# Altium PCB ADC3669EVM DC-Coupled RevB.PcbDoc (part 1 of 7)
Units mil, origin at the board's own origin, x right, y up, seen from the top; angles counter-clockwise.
Board outline 5000 x 2716.54 mil, 12 copper layers (Top Layer, L2 GND, L3 SIG, L4 GND, L5 PWR, L6 GND, L7 GND, L8 PWR, L9 GND, L10 PWR, L11 GND, Bottom Layer), stack 61 mil thick; 546 components, 341 nets, 2088 pads, 1256 vias.
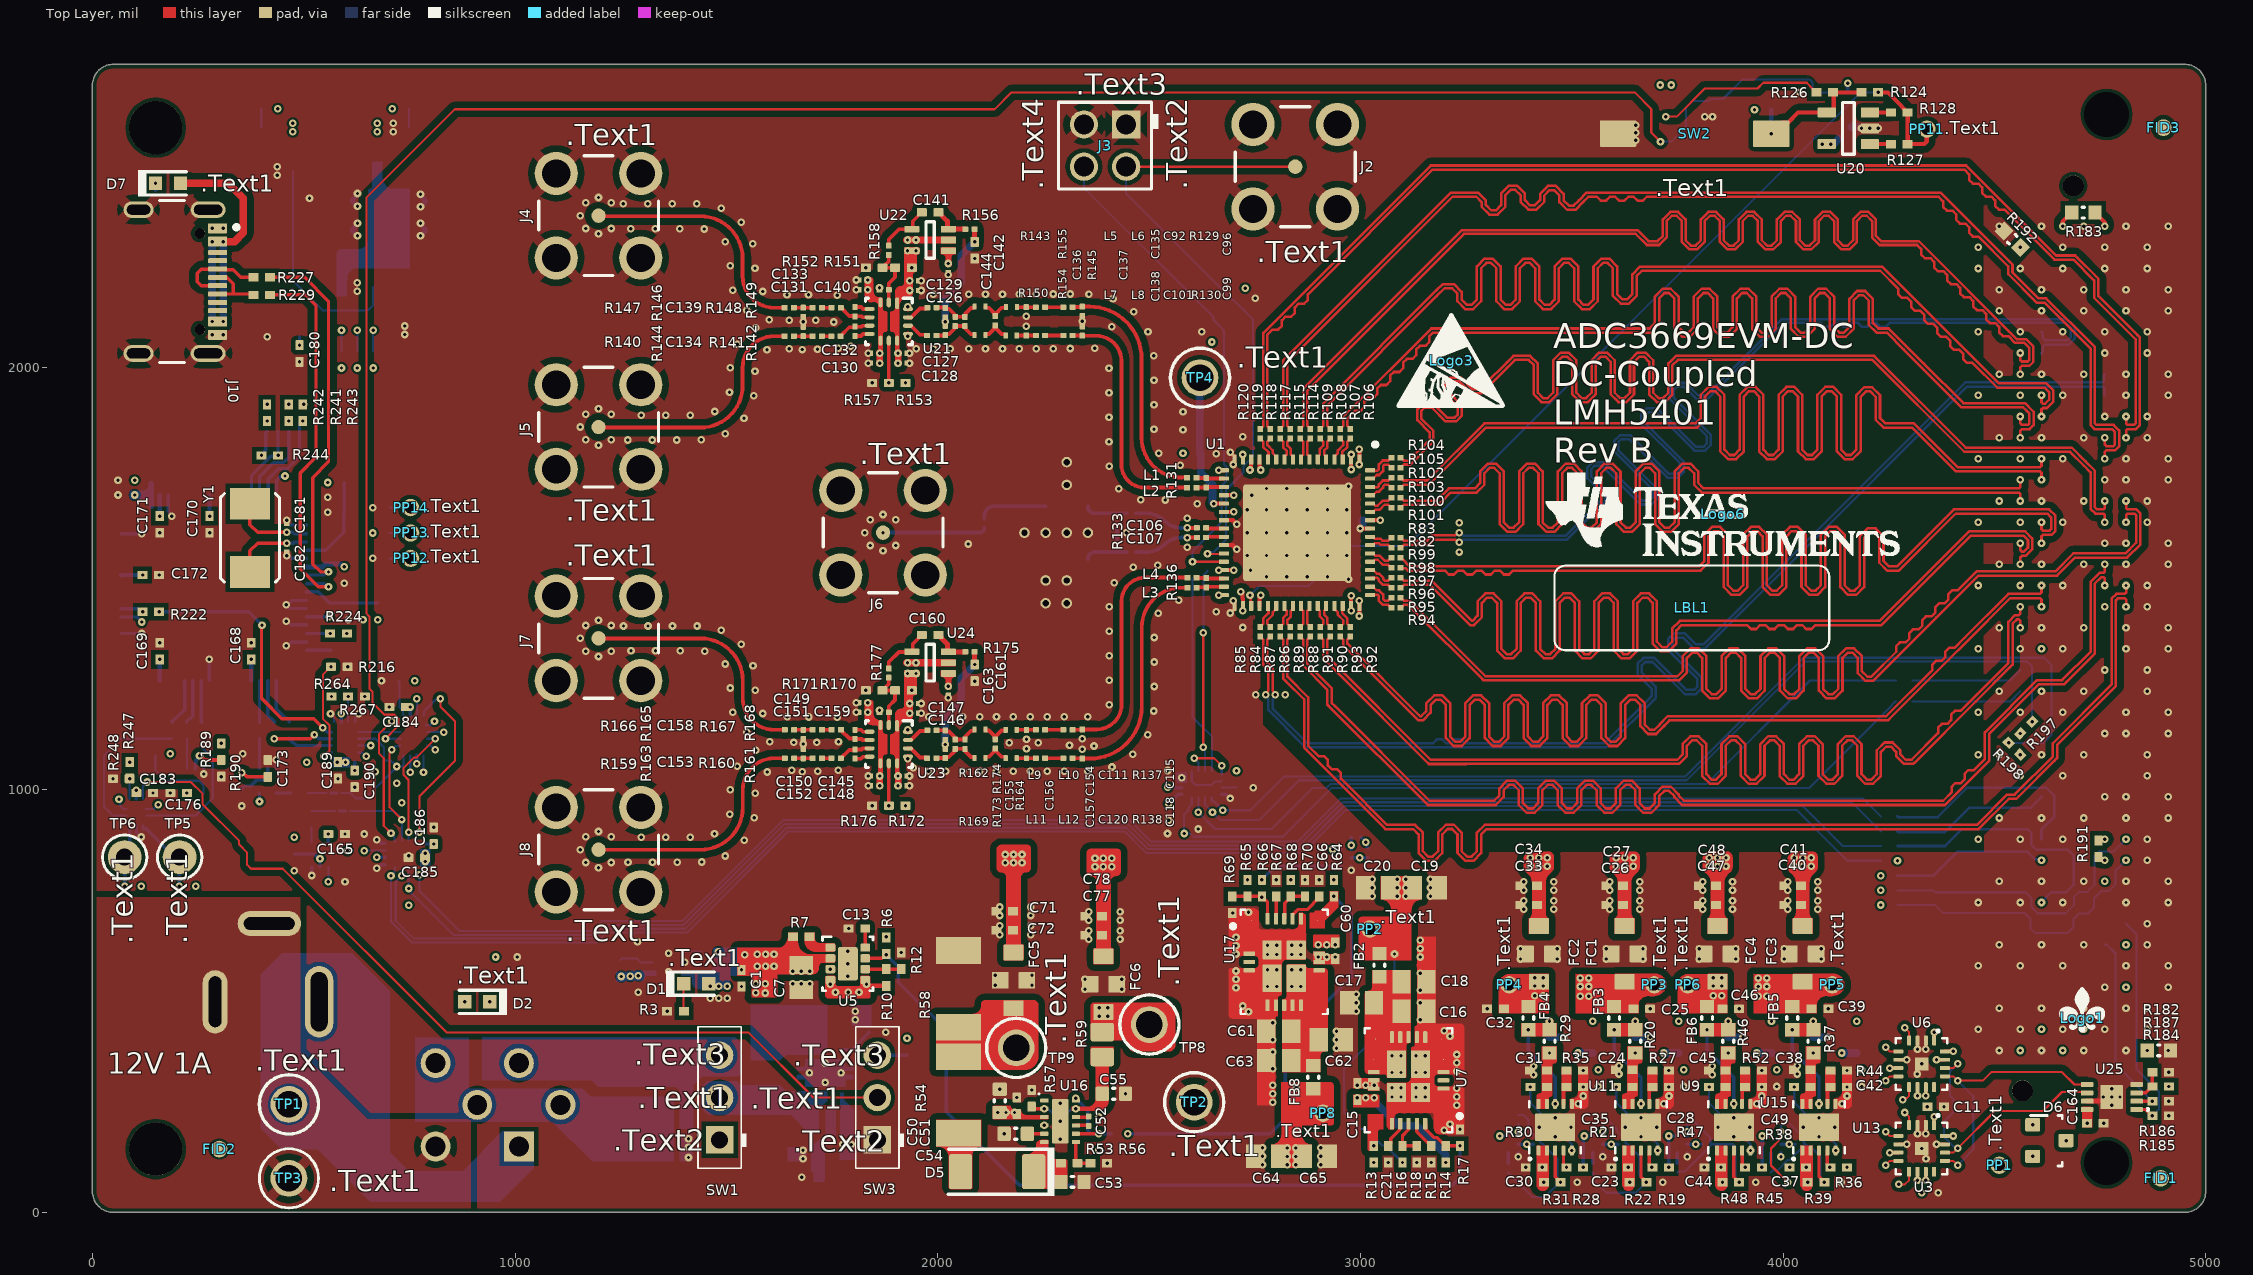
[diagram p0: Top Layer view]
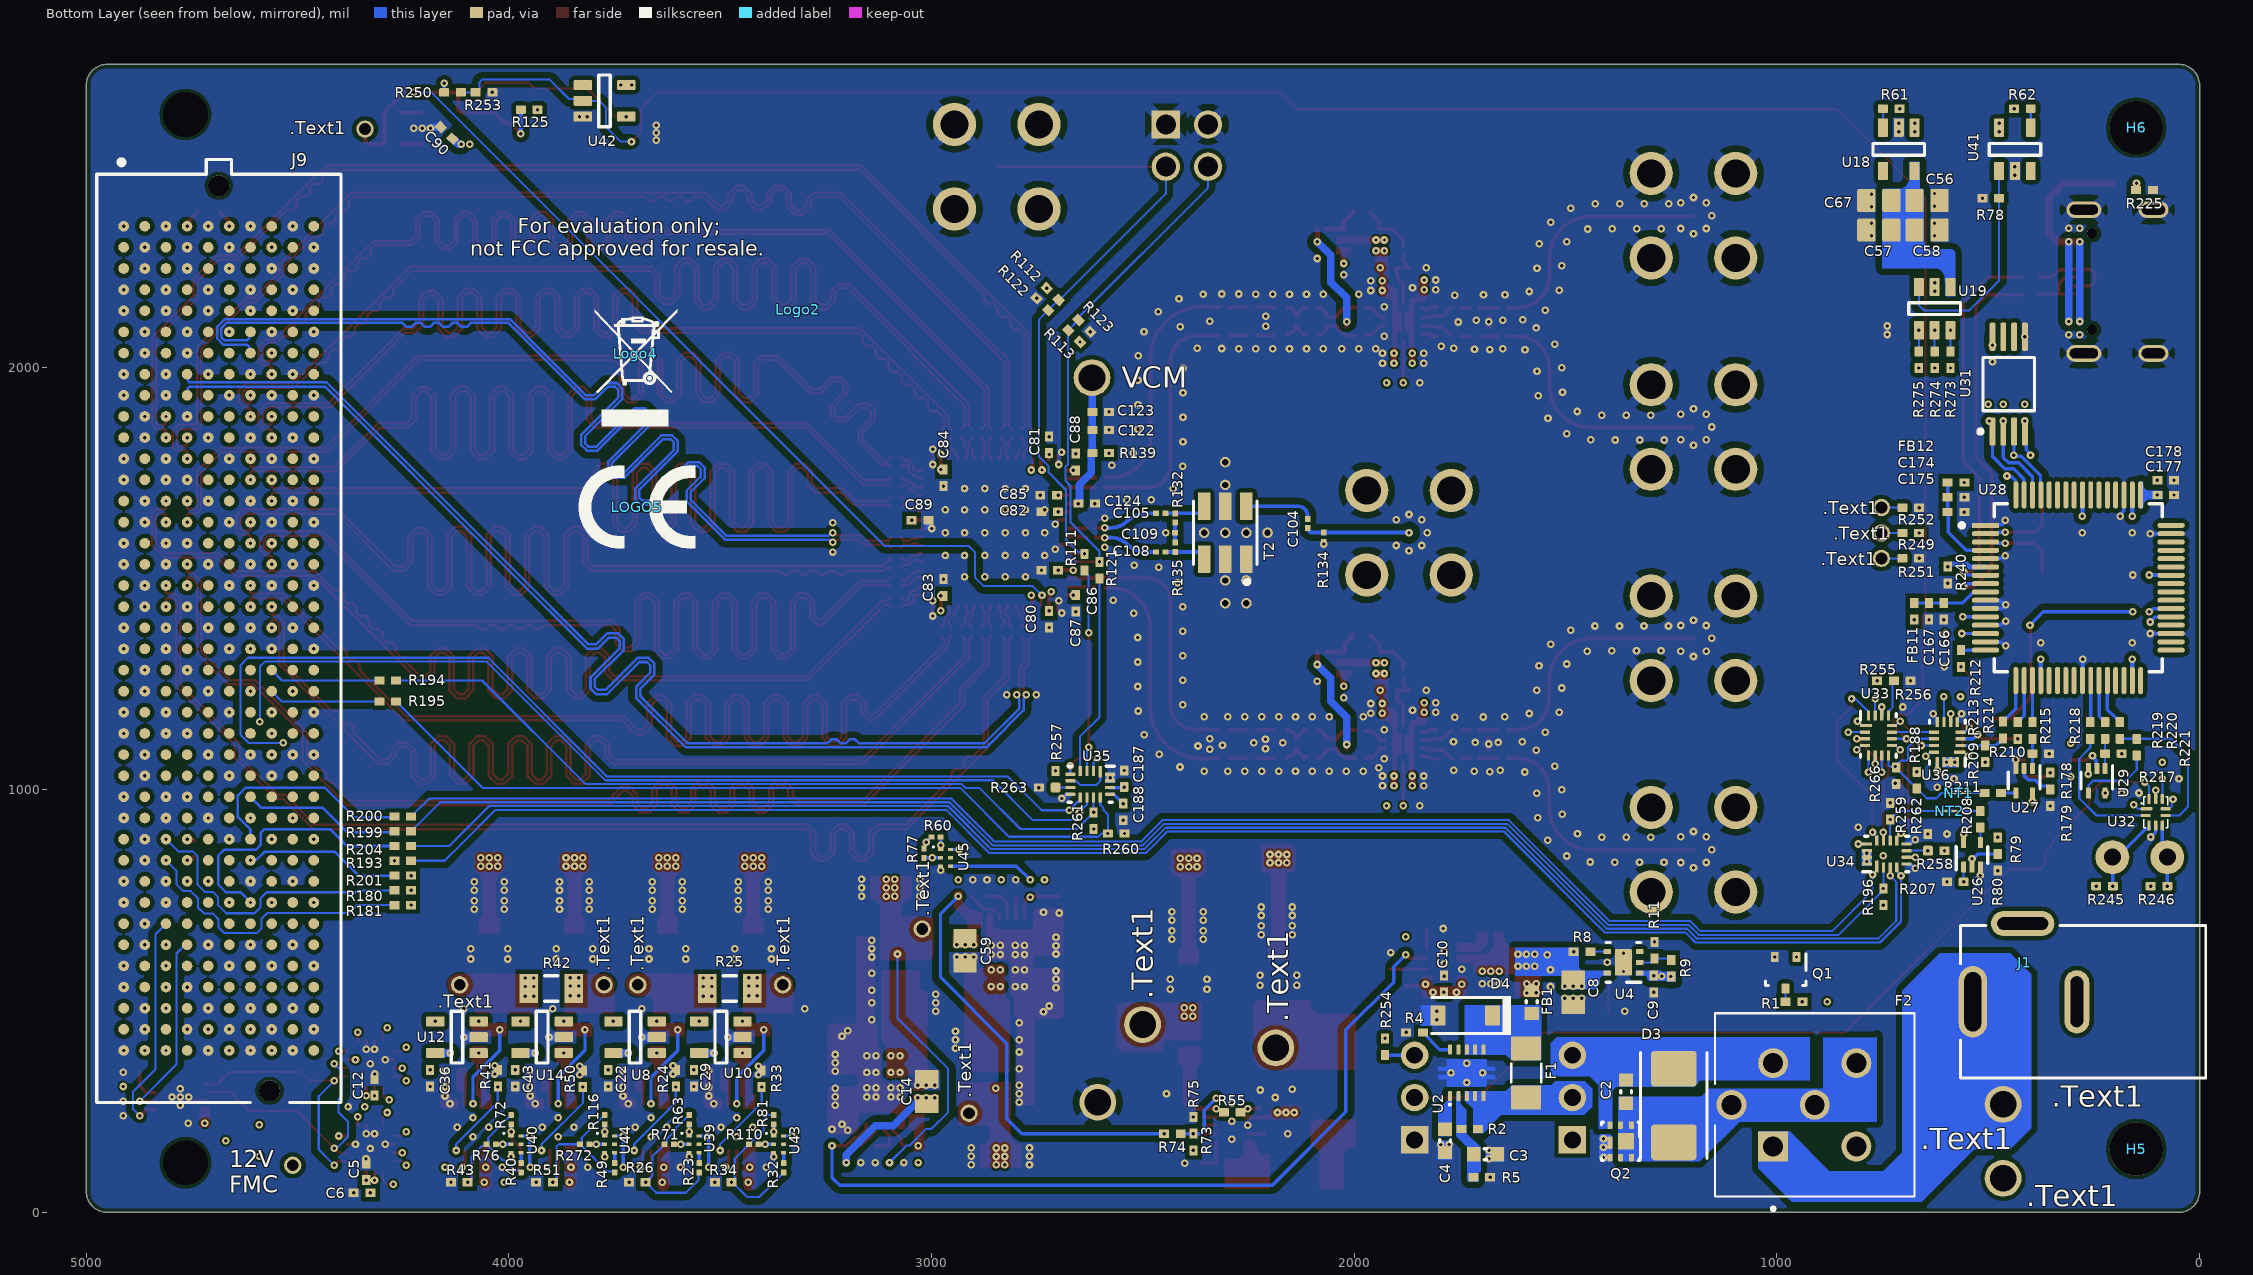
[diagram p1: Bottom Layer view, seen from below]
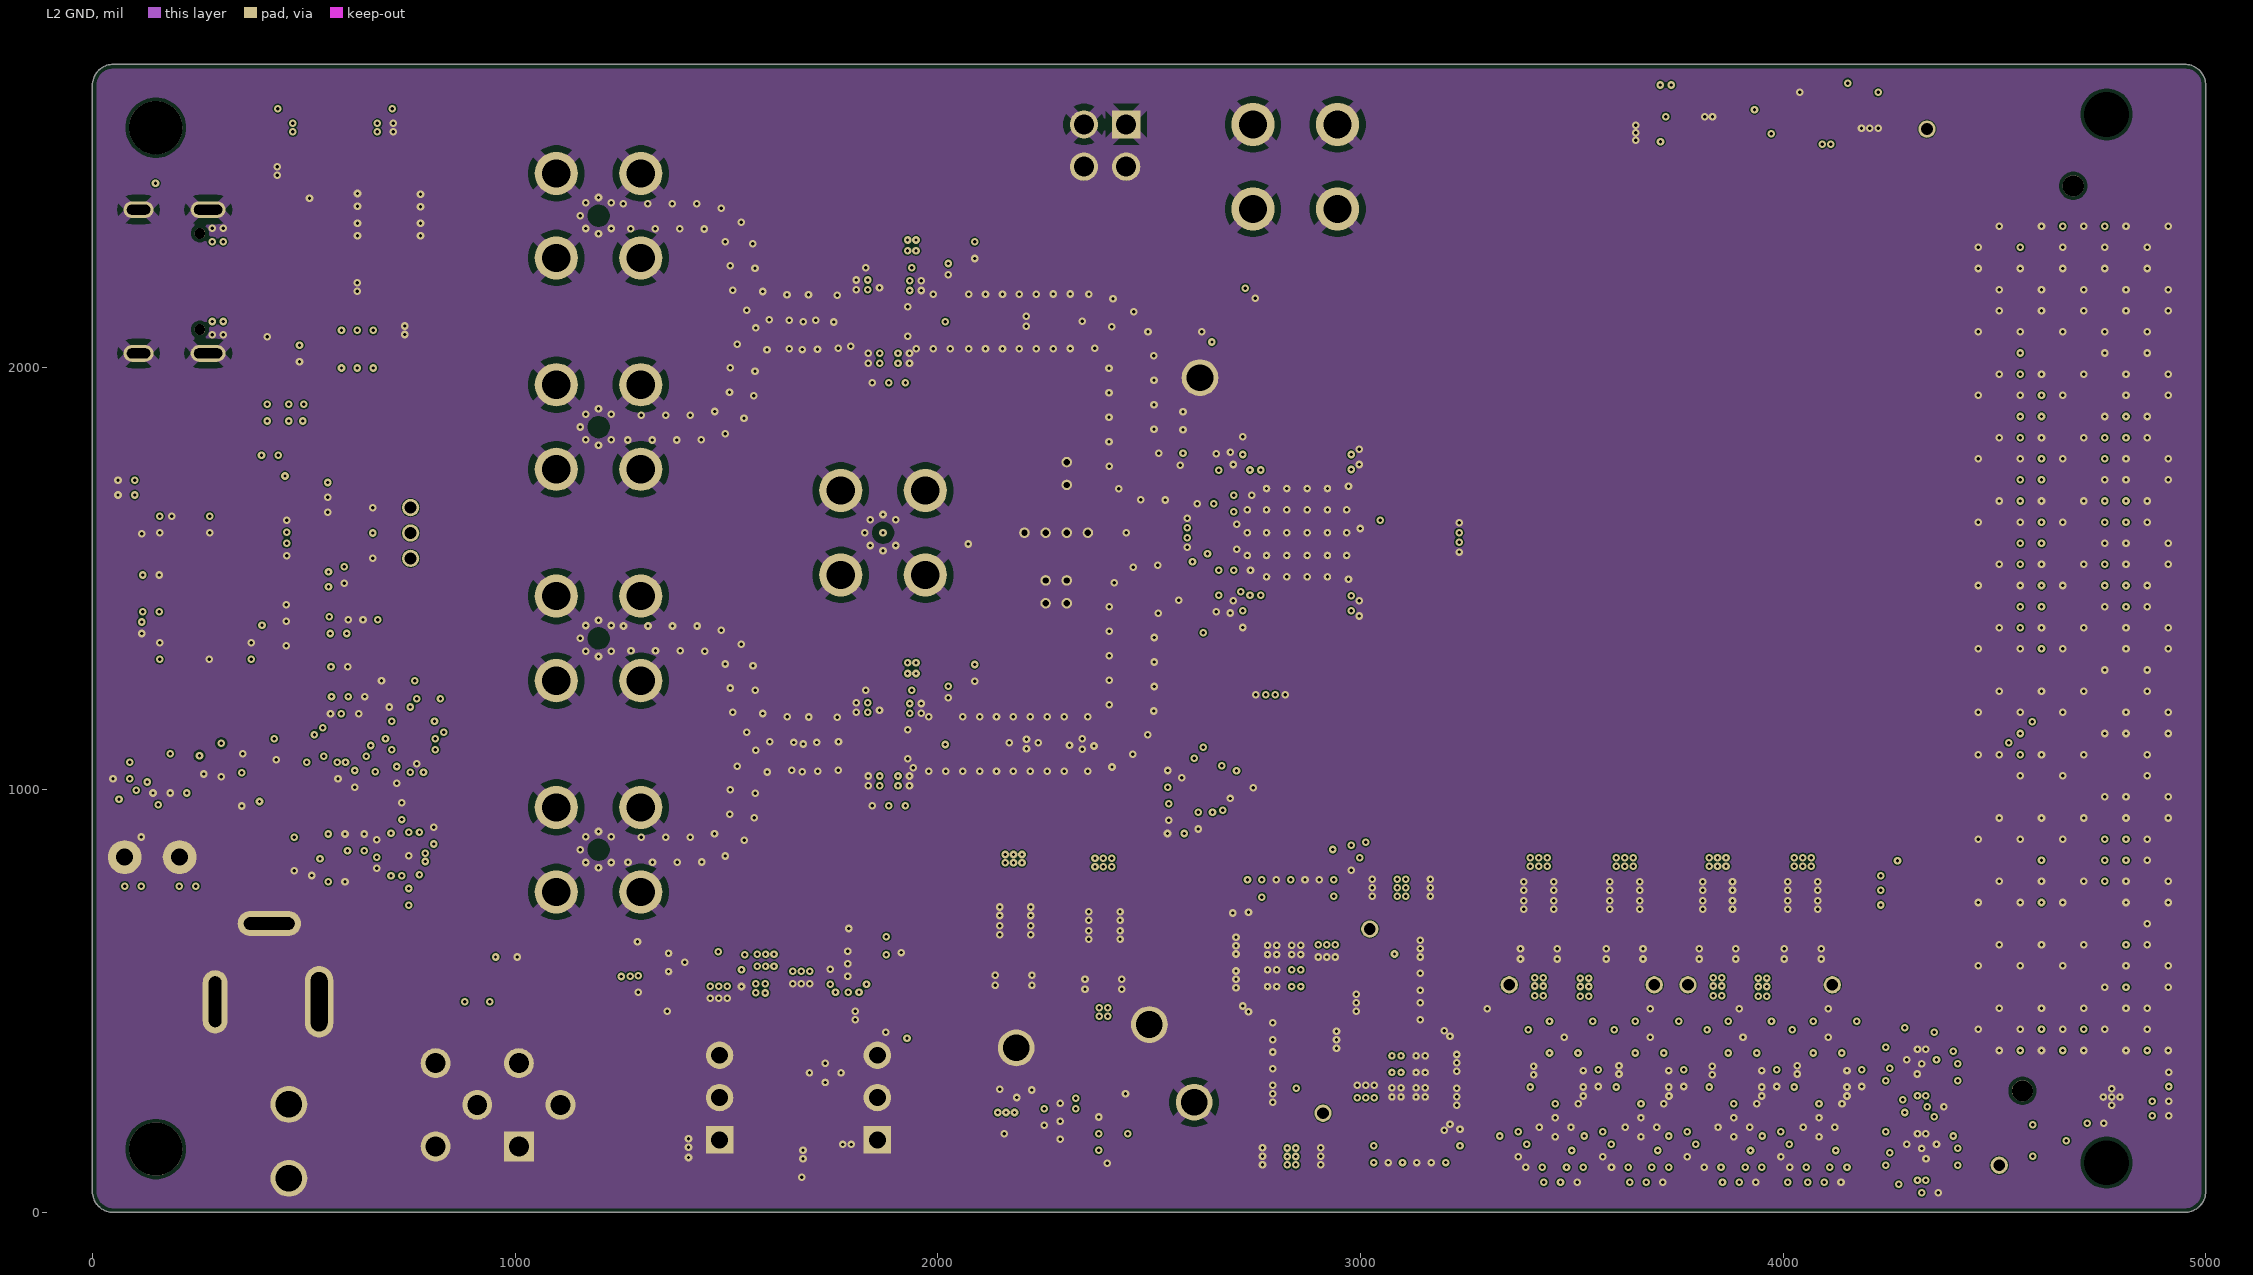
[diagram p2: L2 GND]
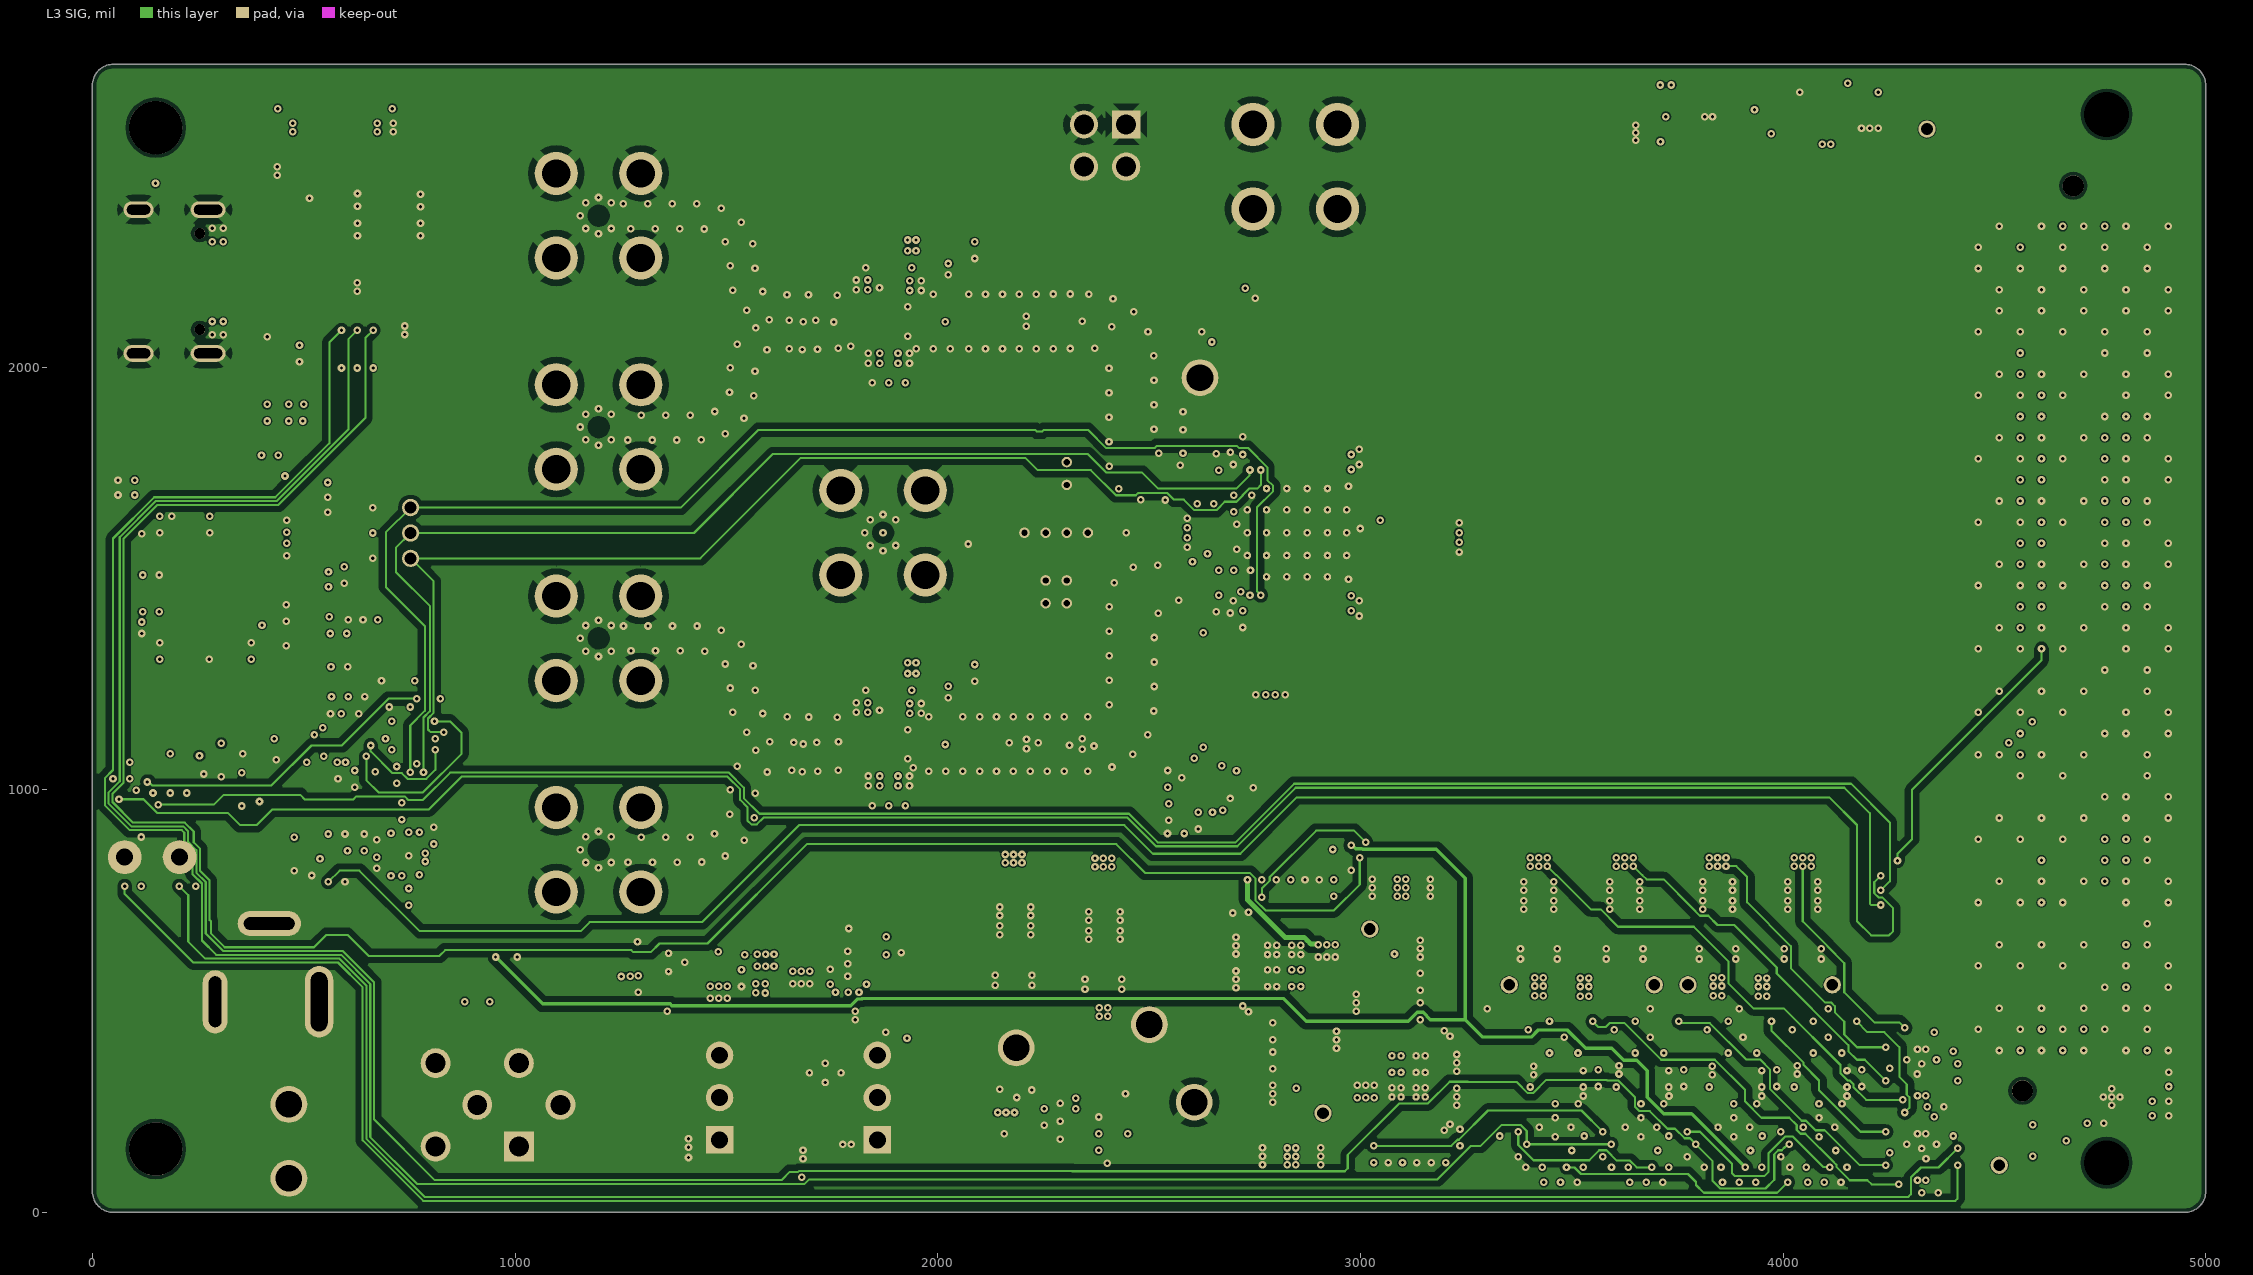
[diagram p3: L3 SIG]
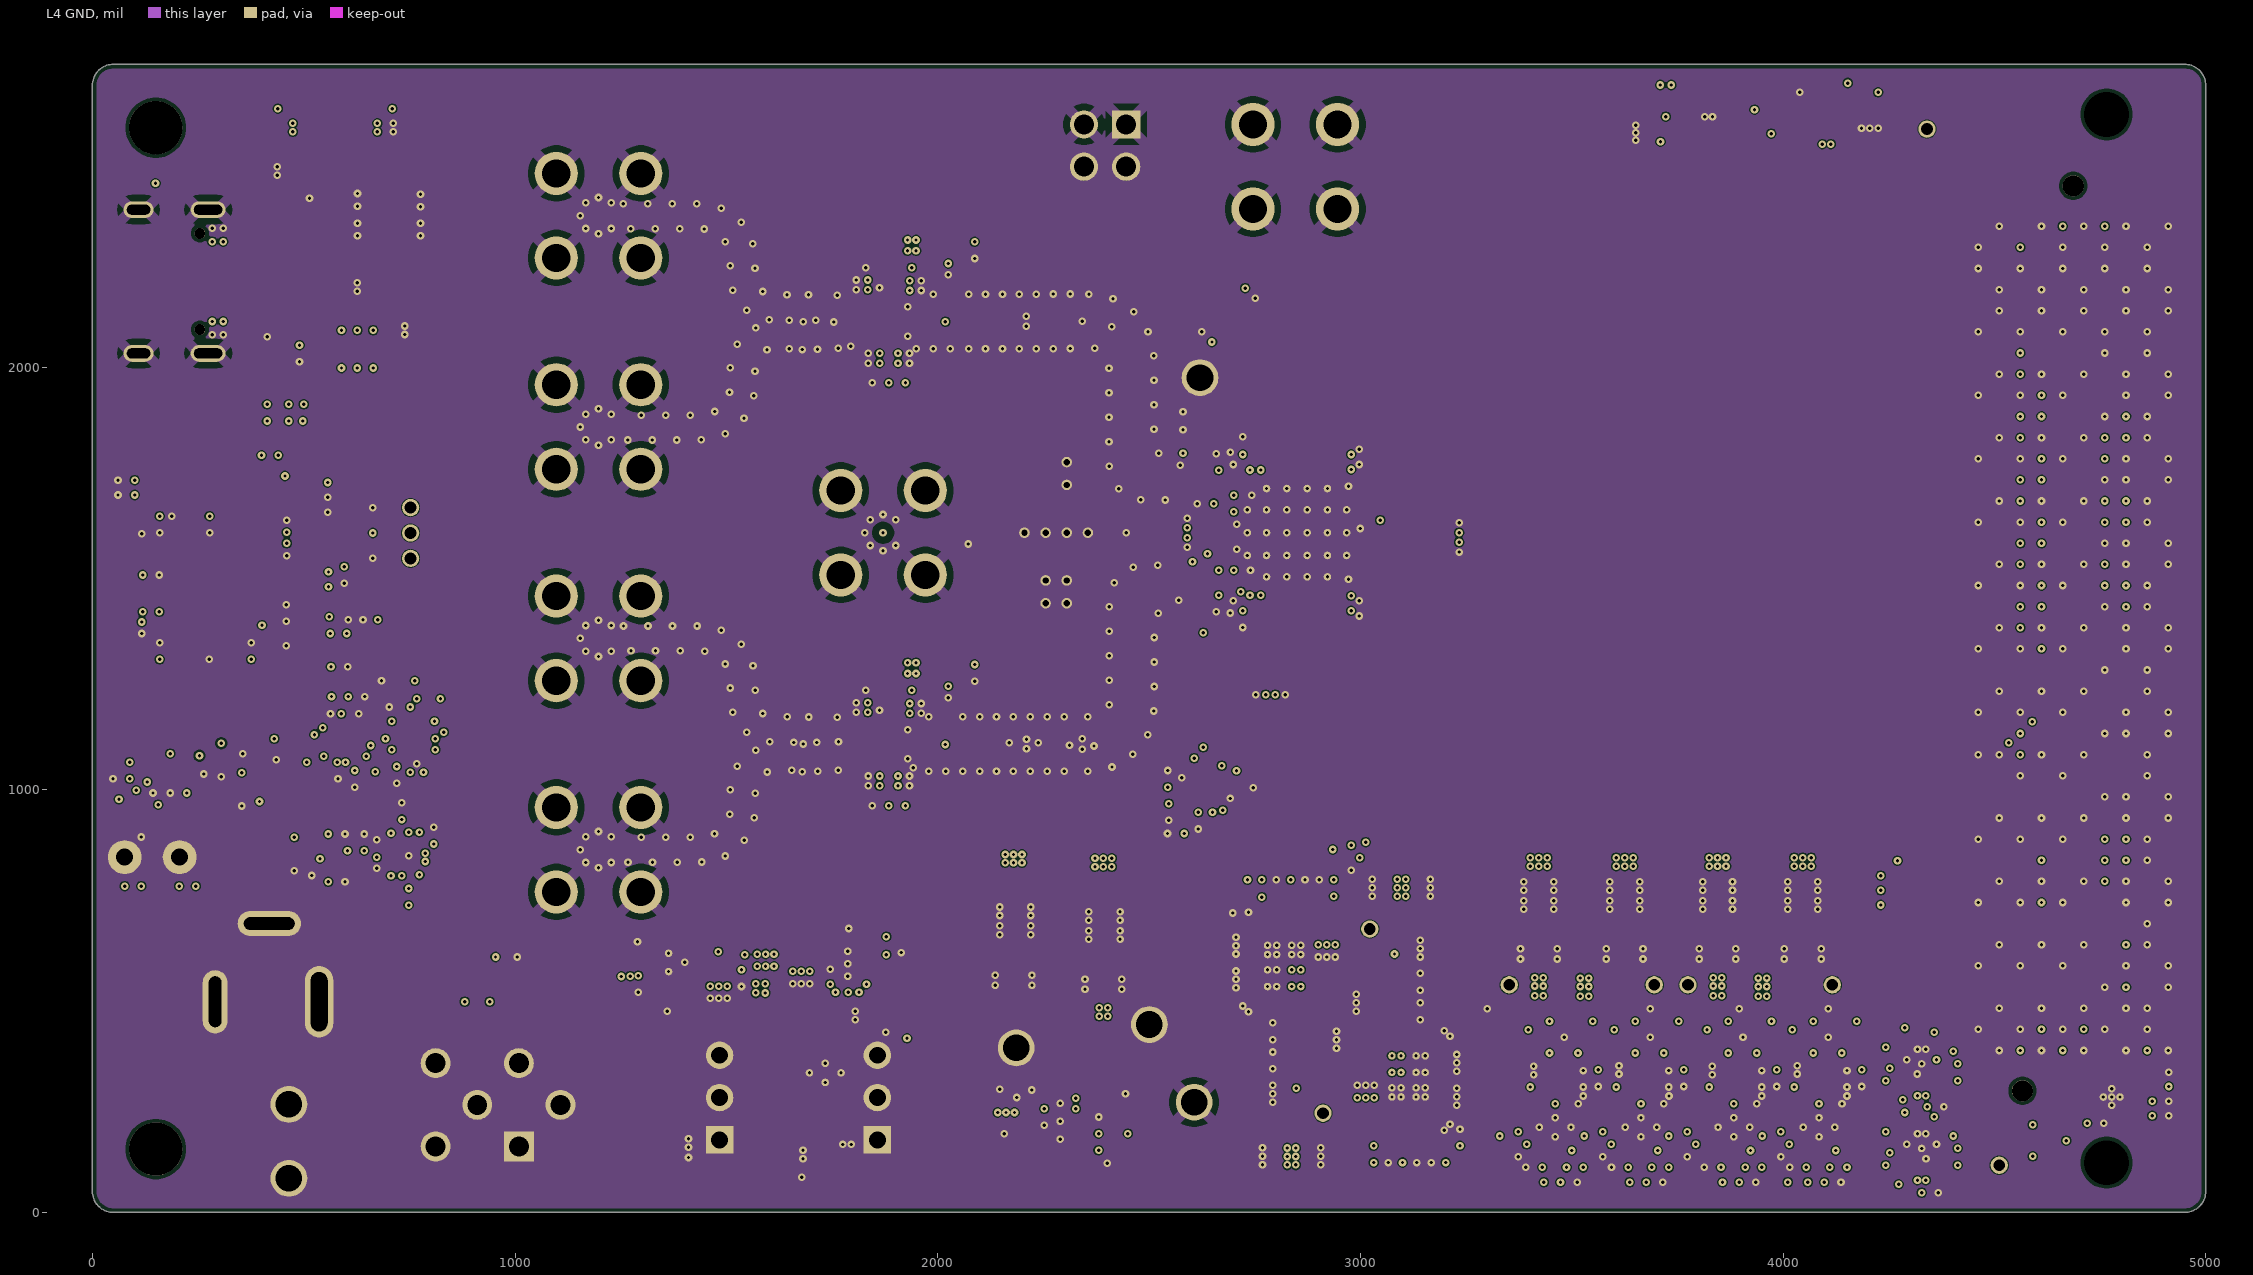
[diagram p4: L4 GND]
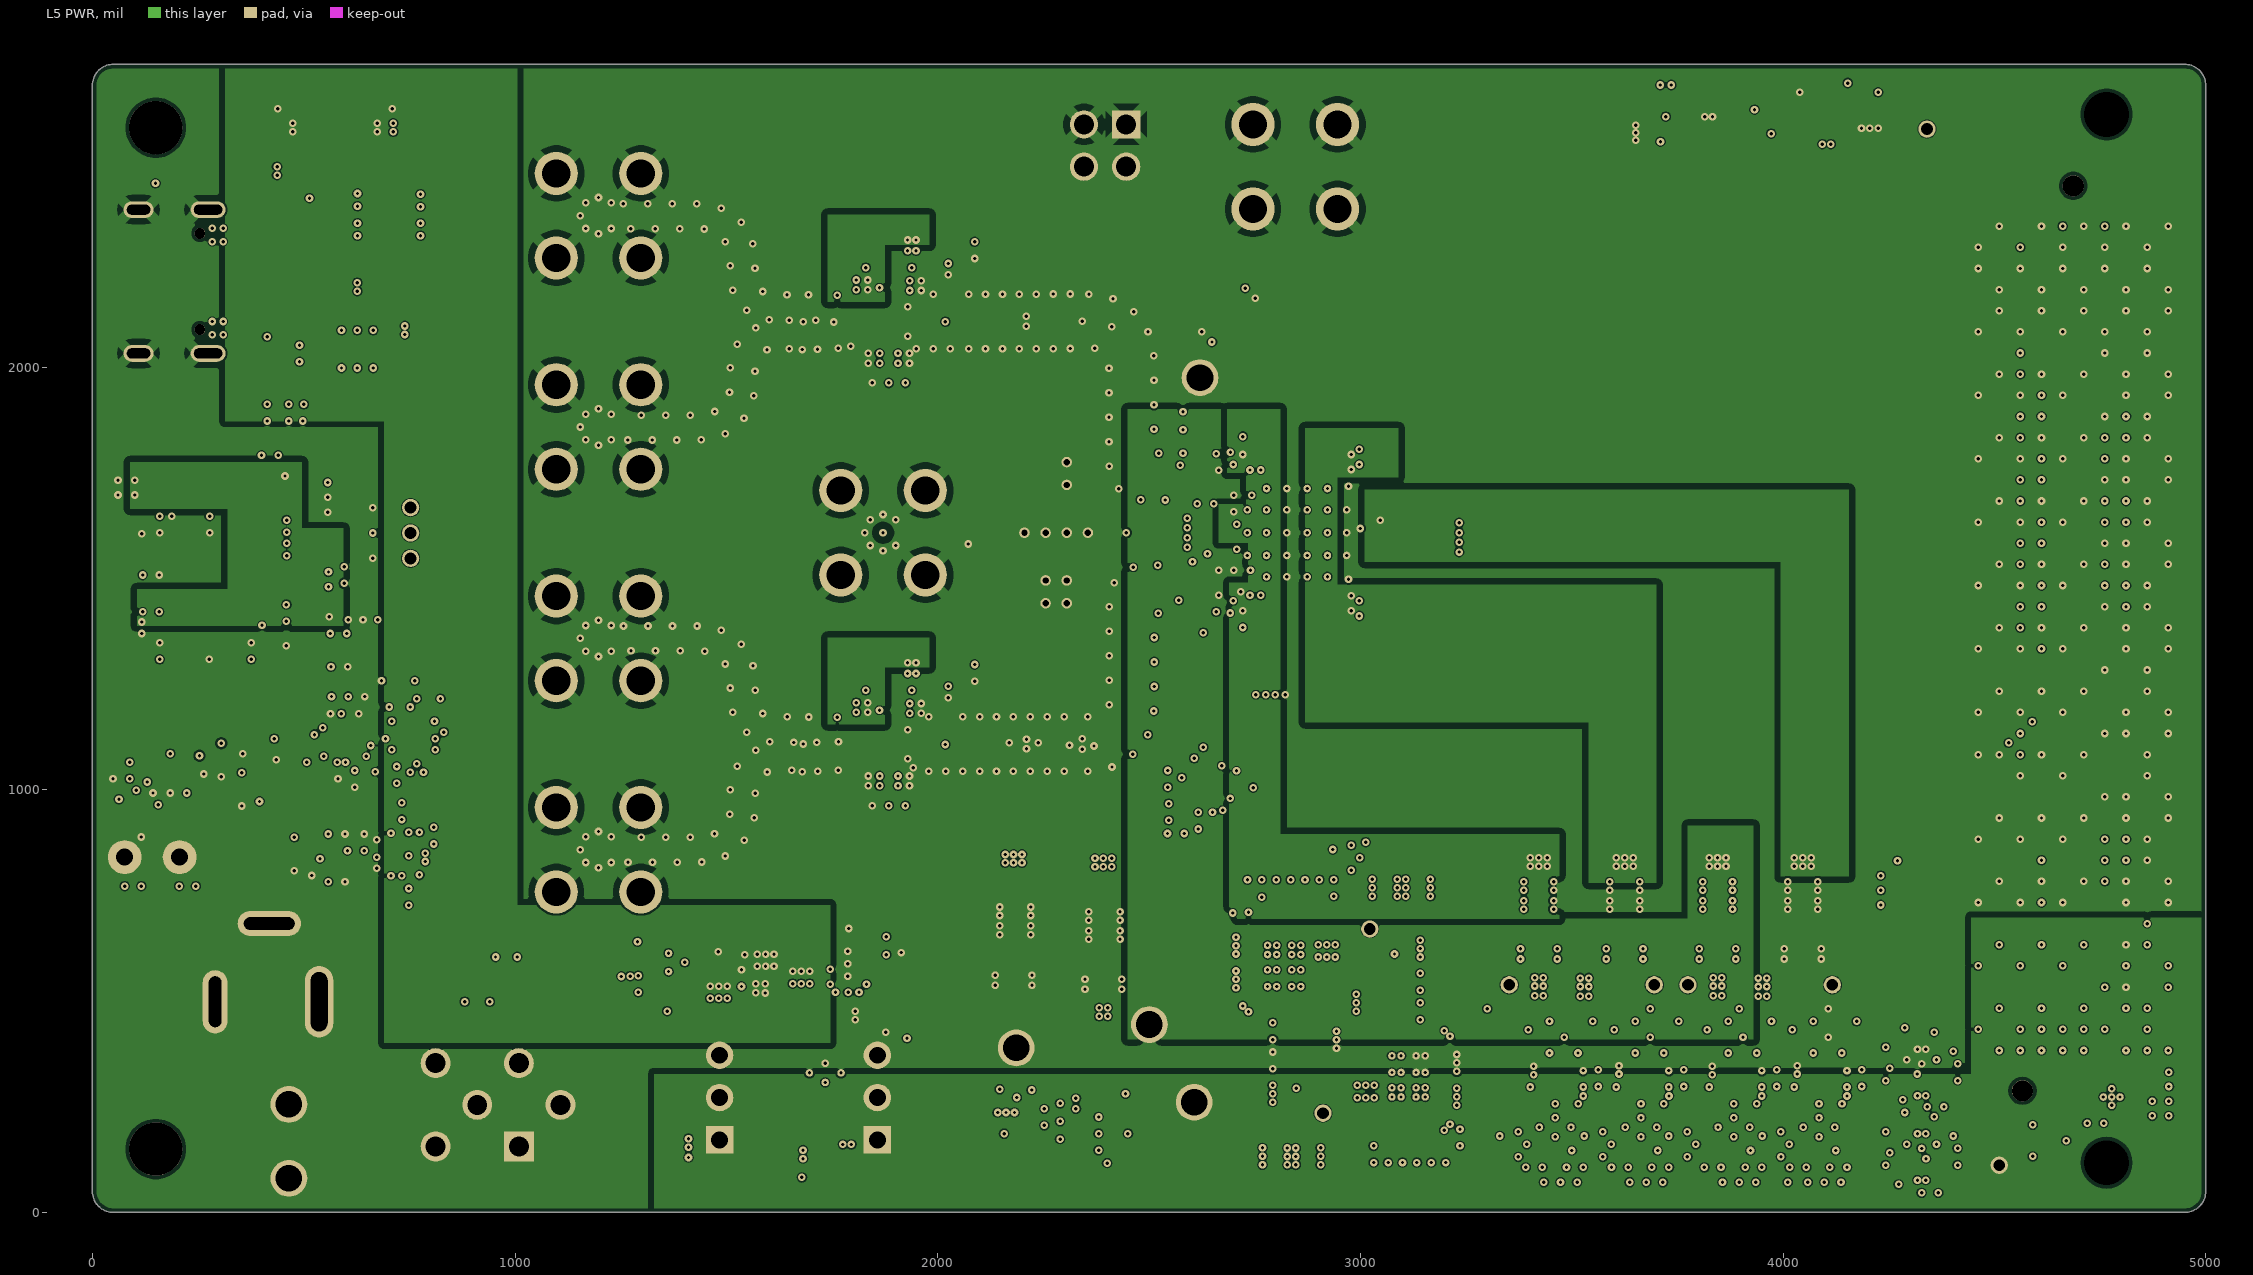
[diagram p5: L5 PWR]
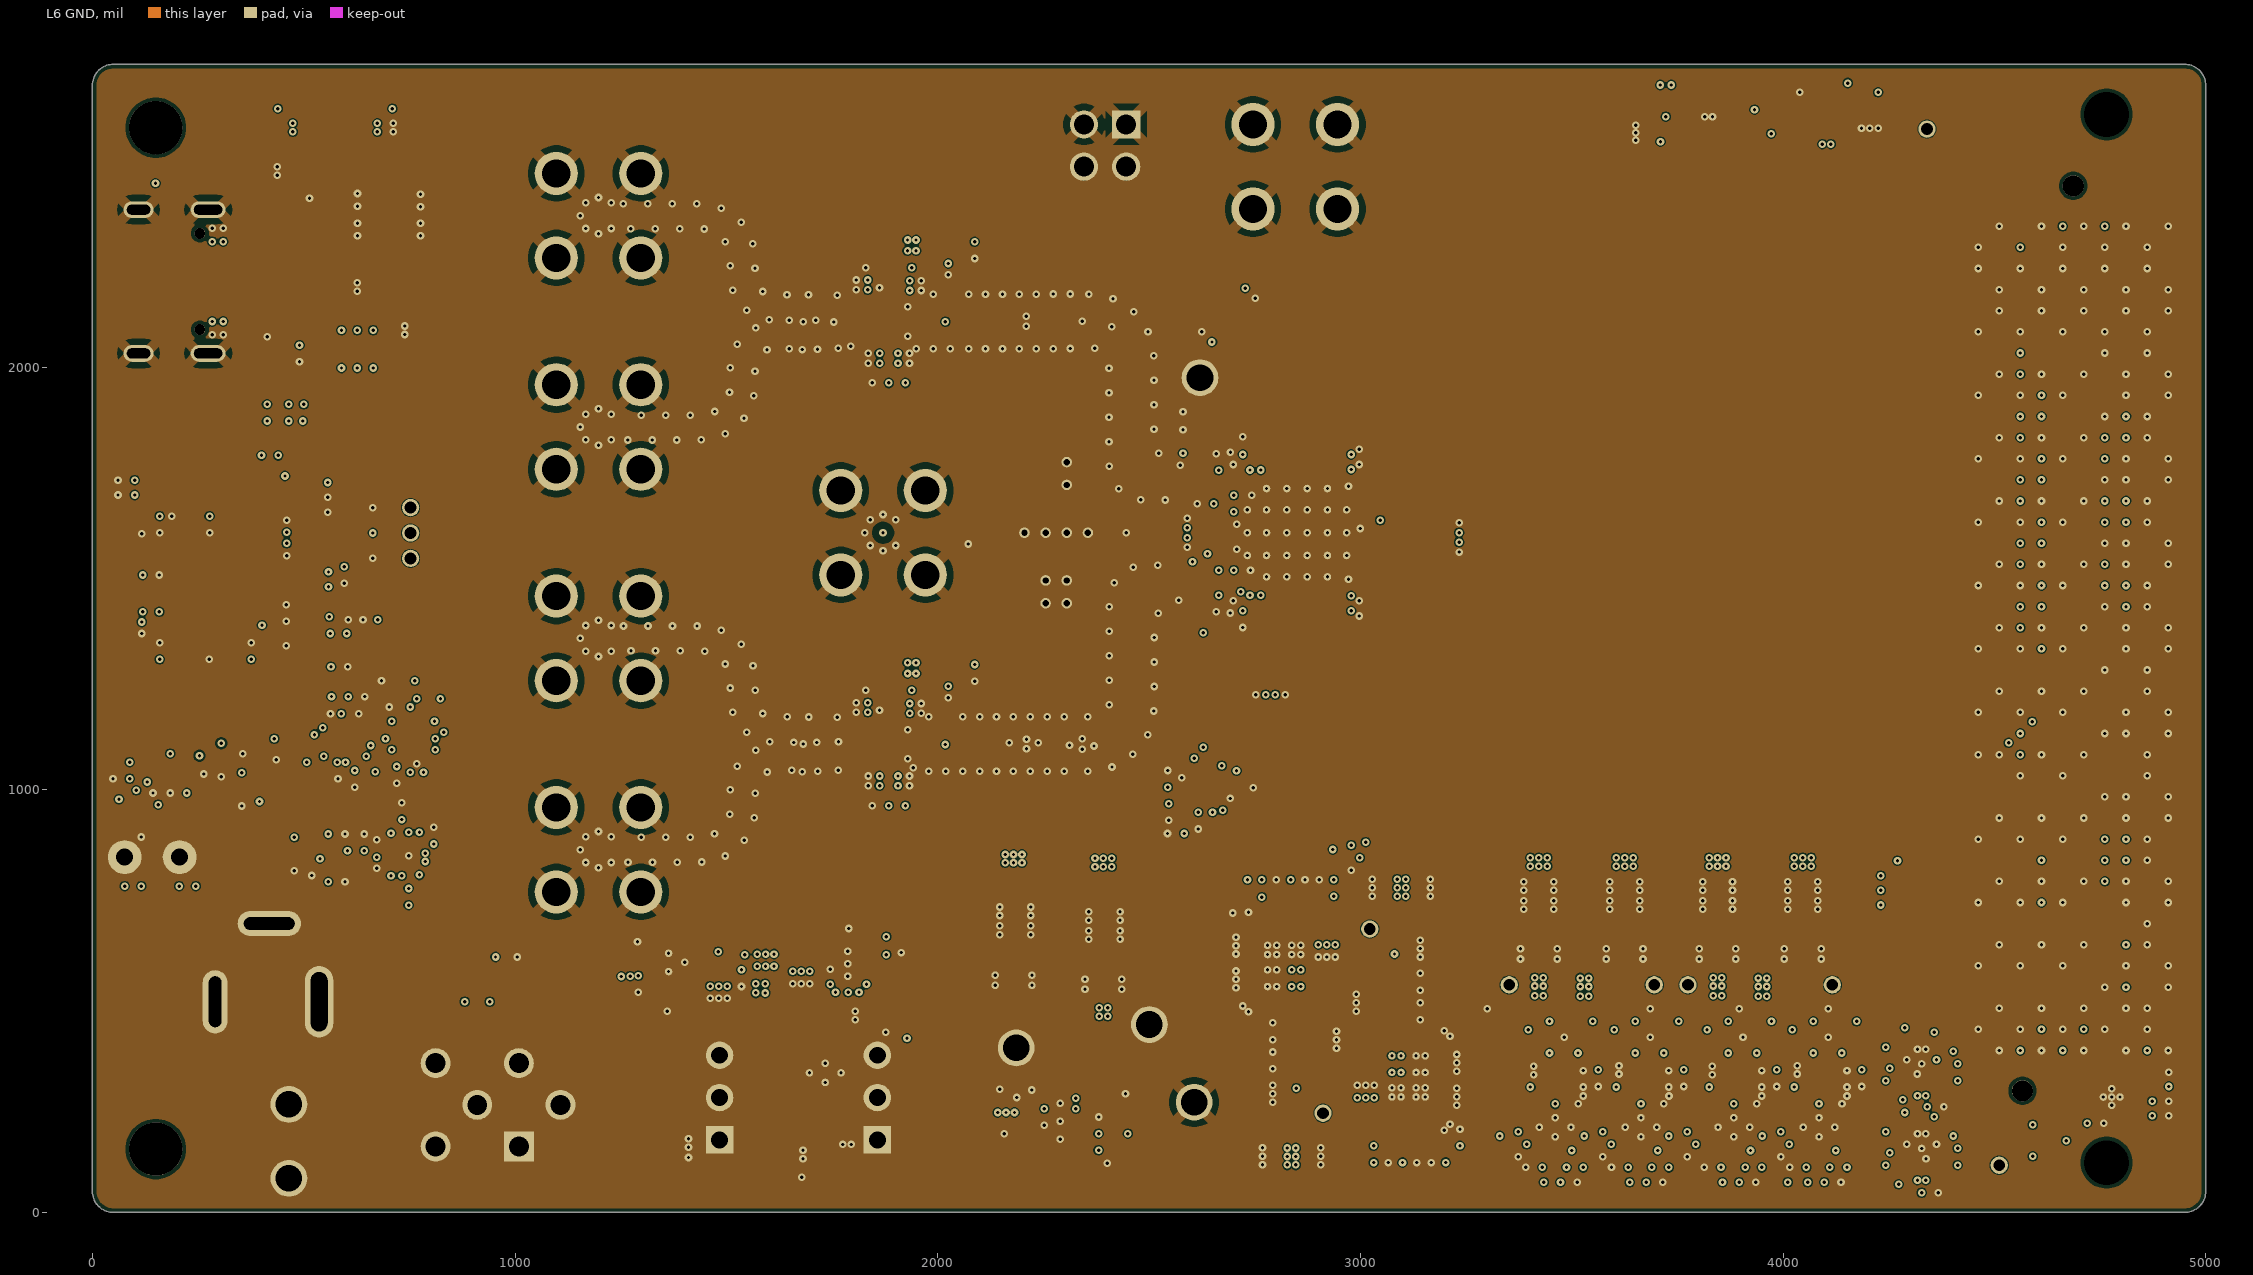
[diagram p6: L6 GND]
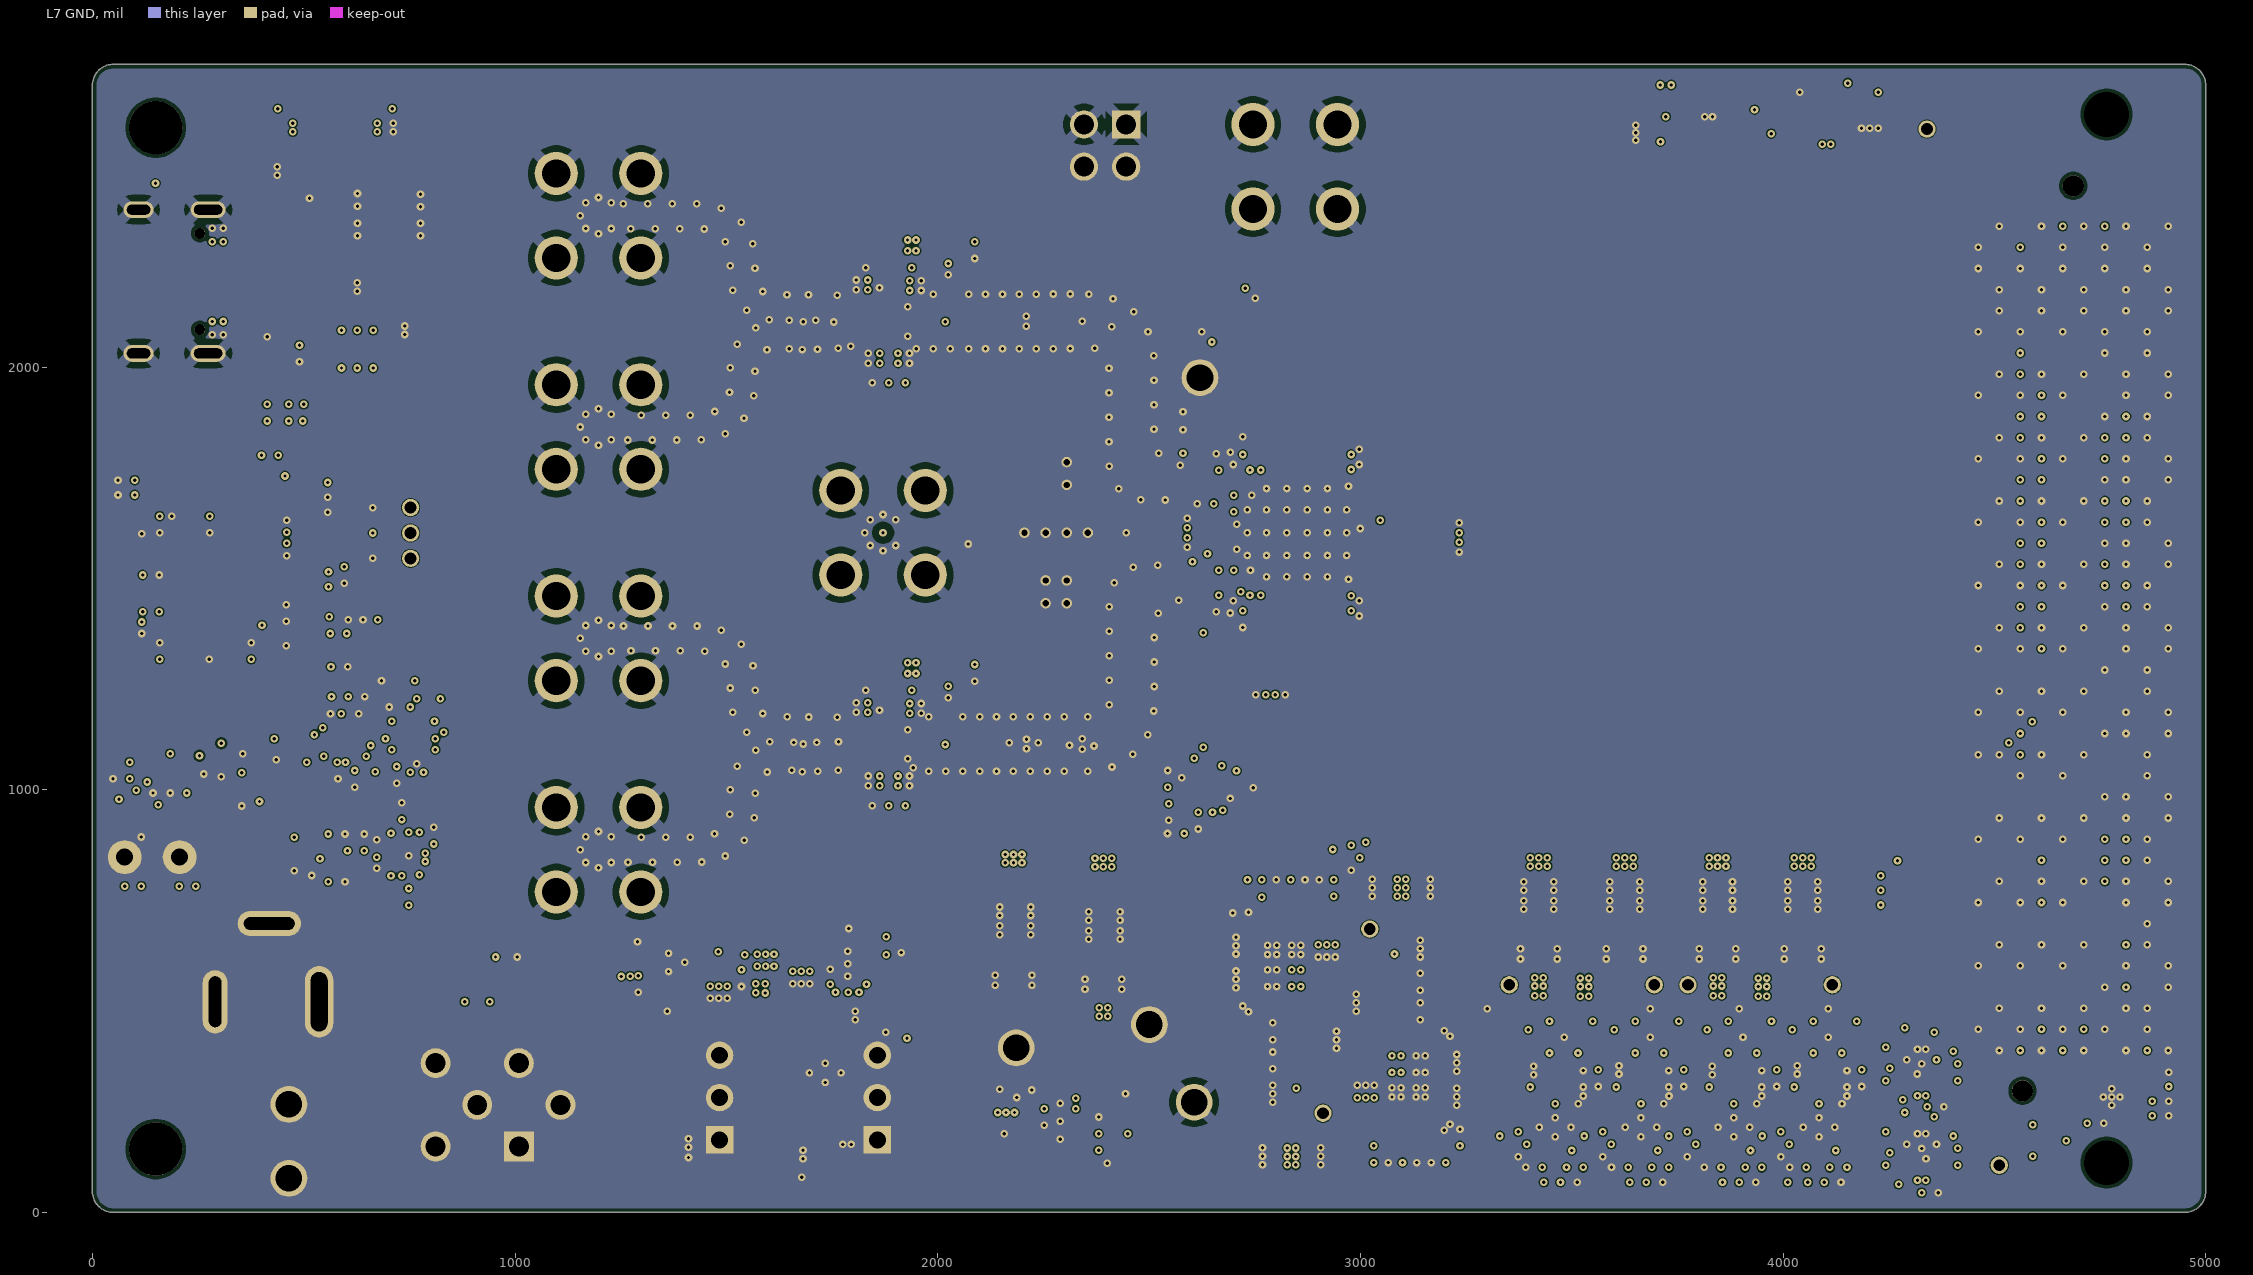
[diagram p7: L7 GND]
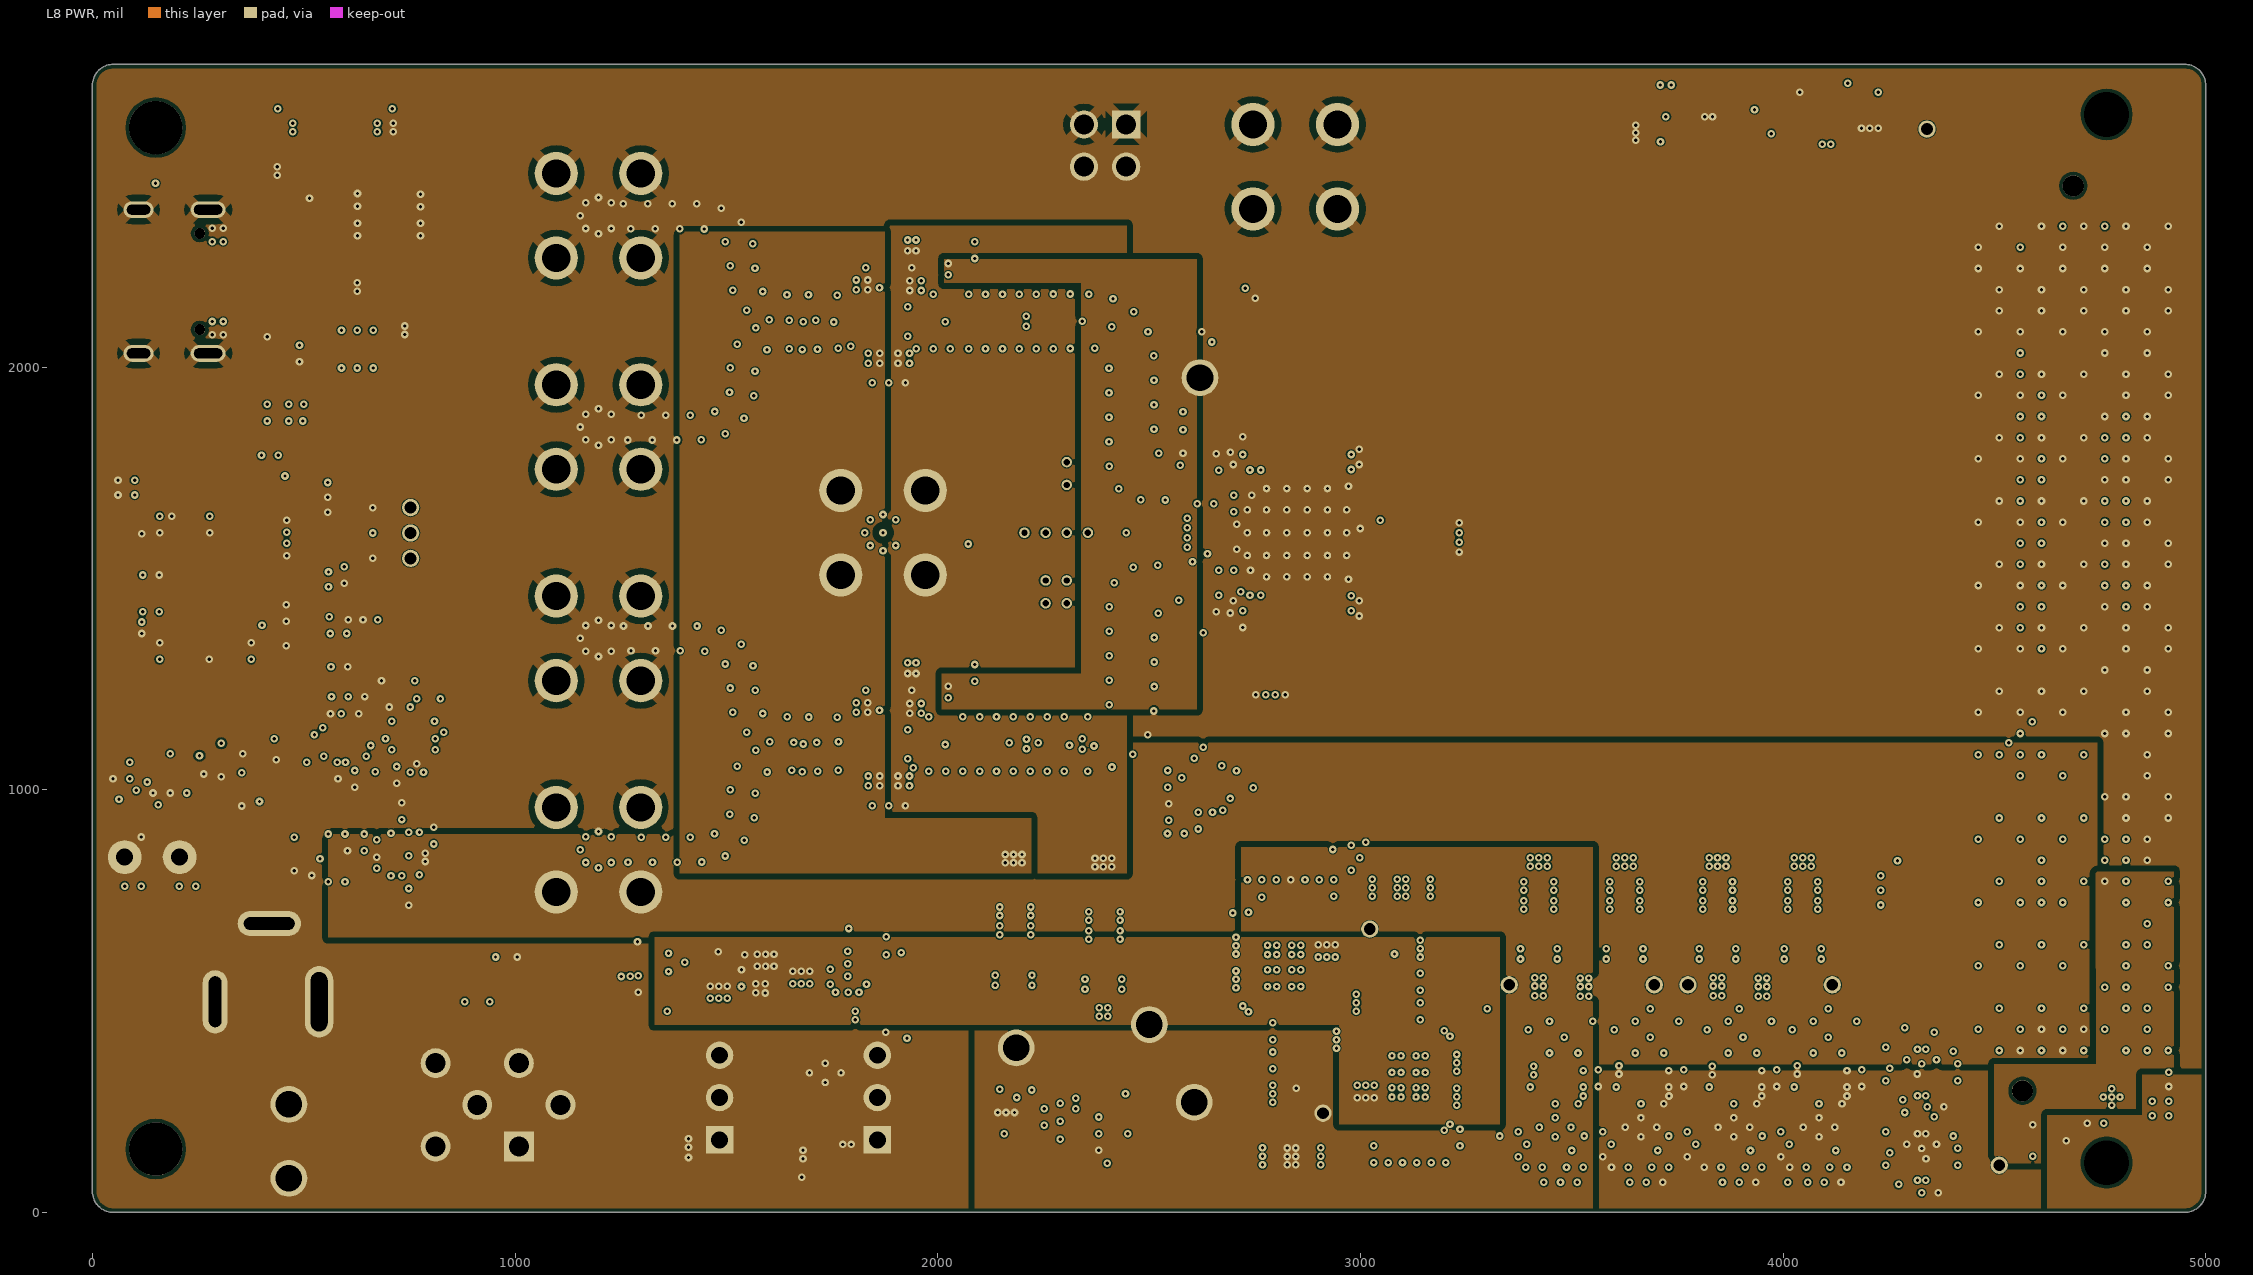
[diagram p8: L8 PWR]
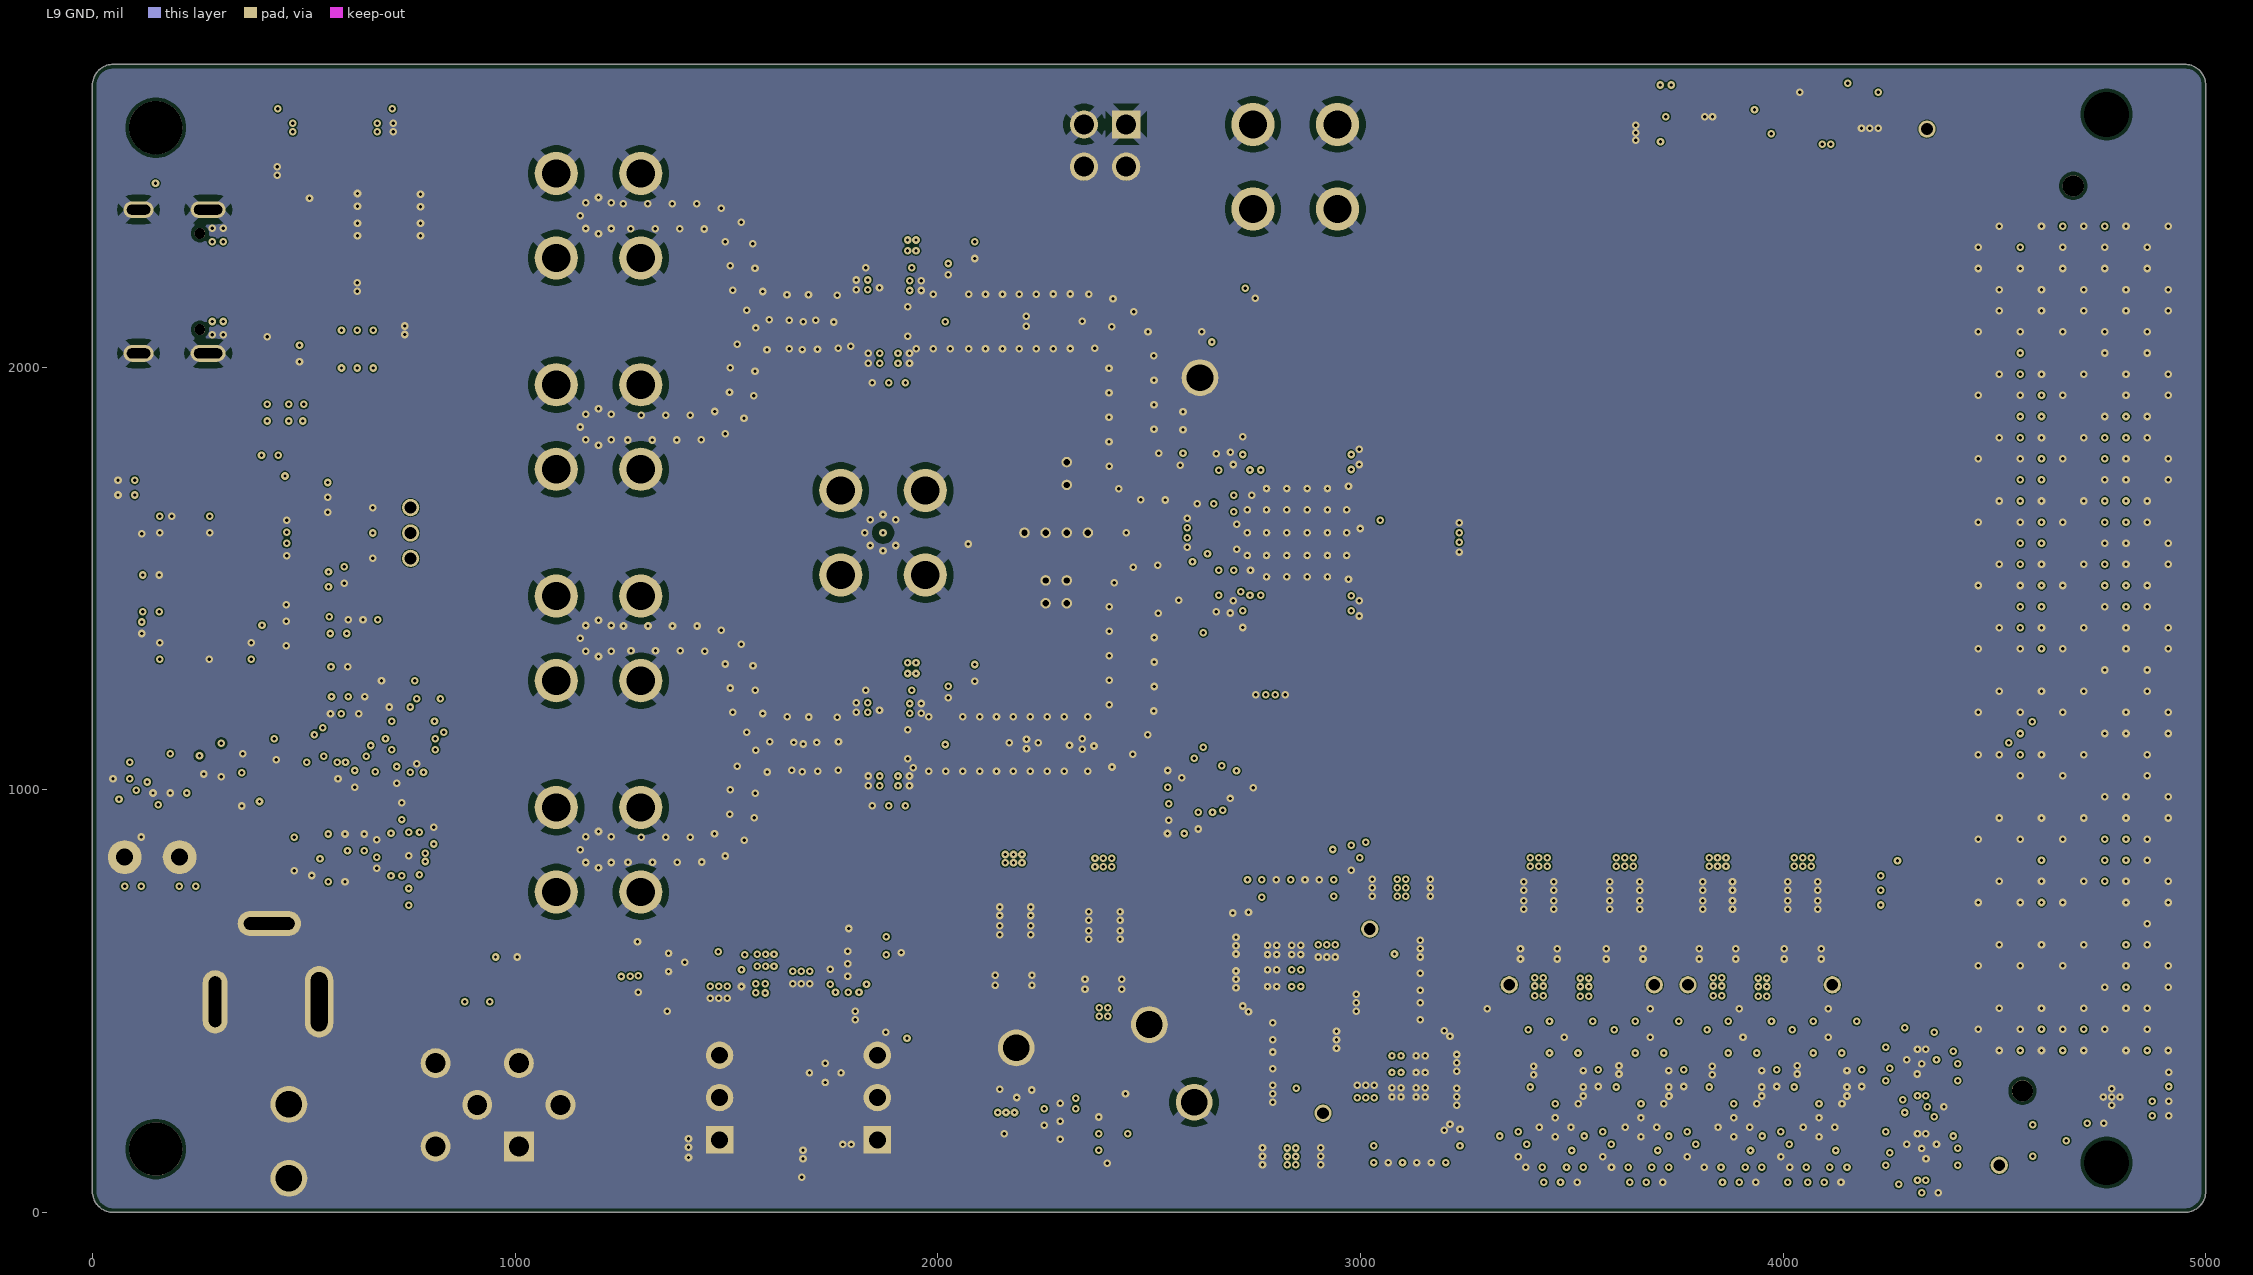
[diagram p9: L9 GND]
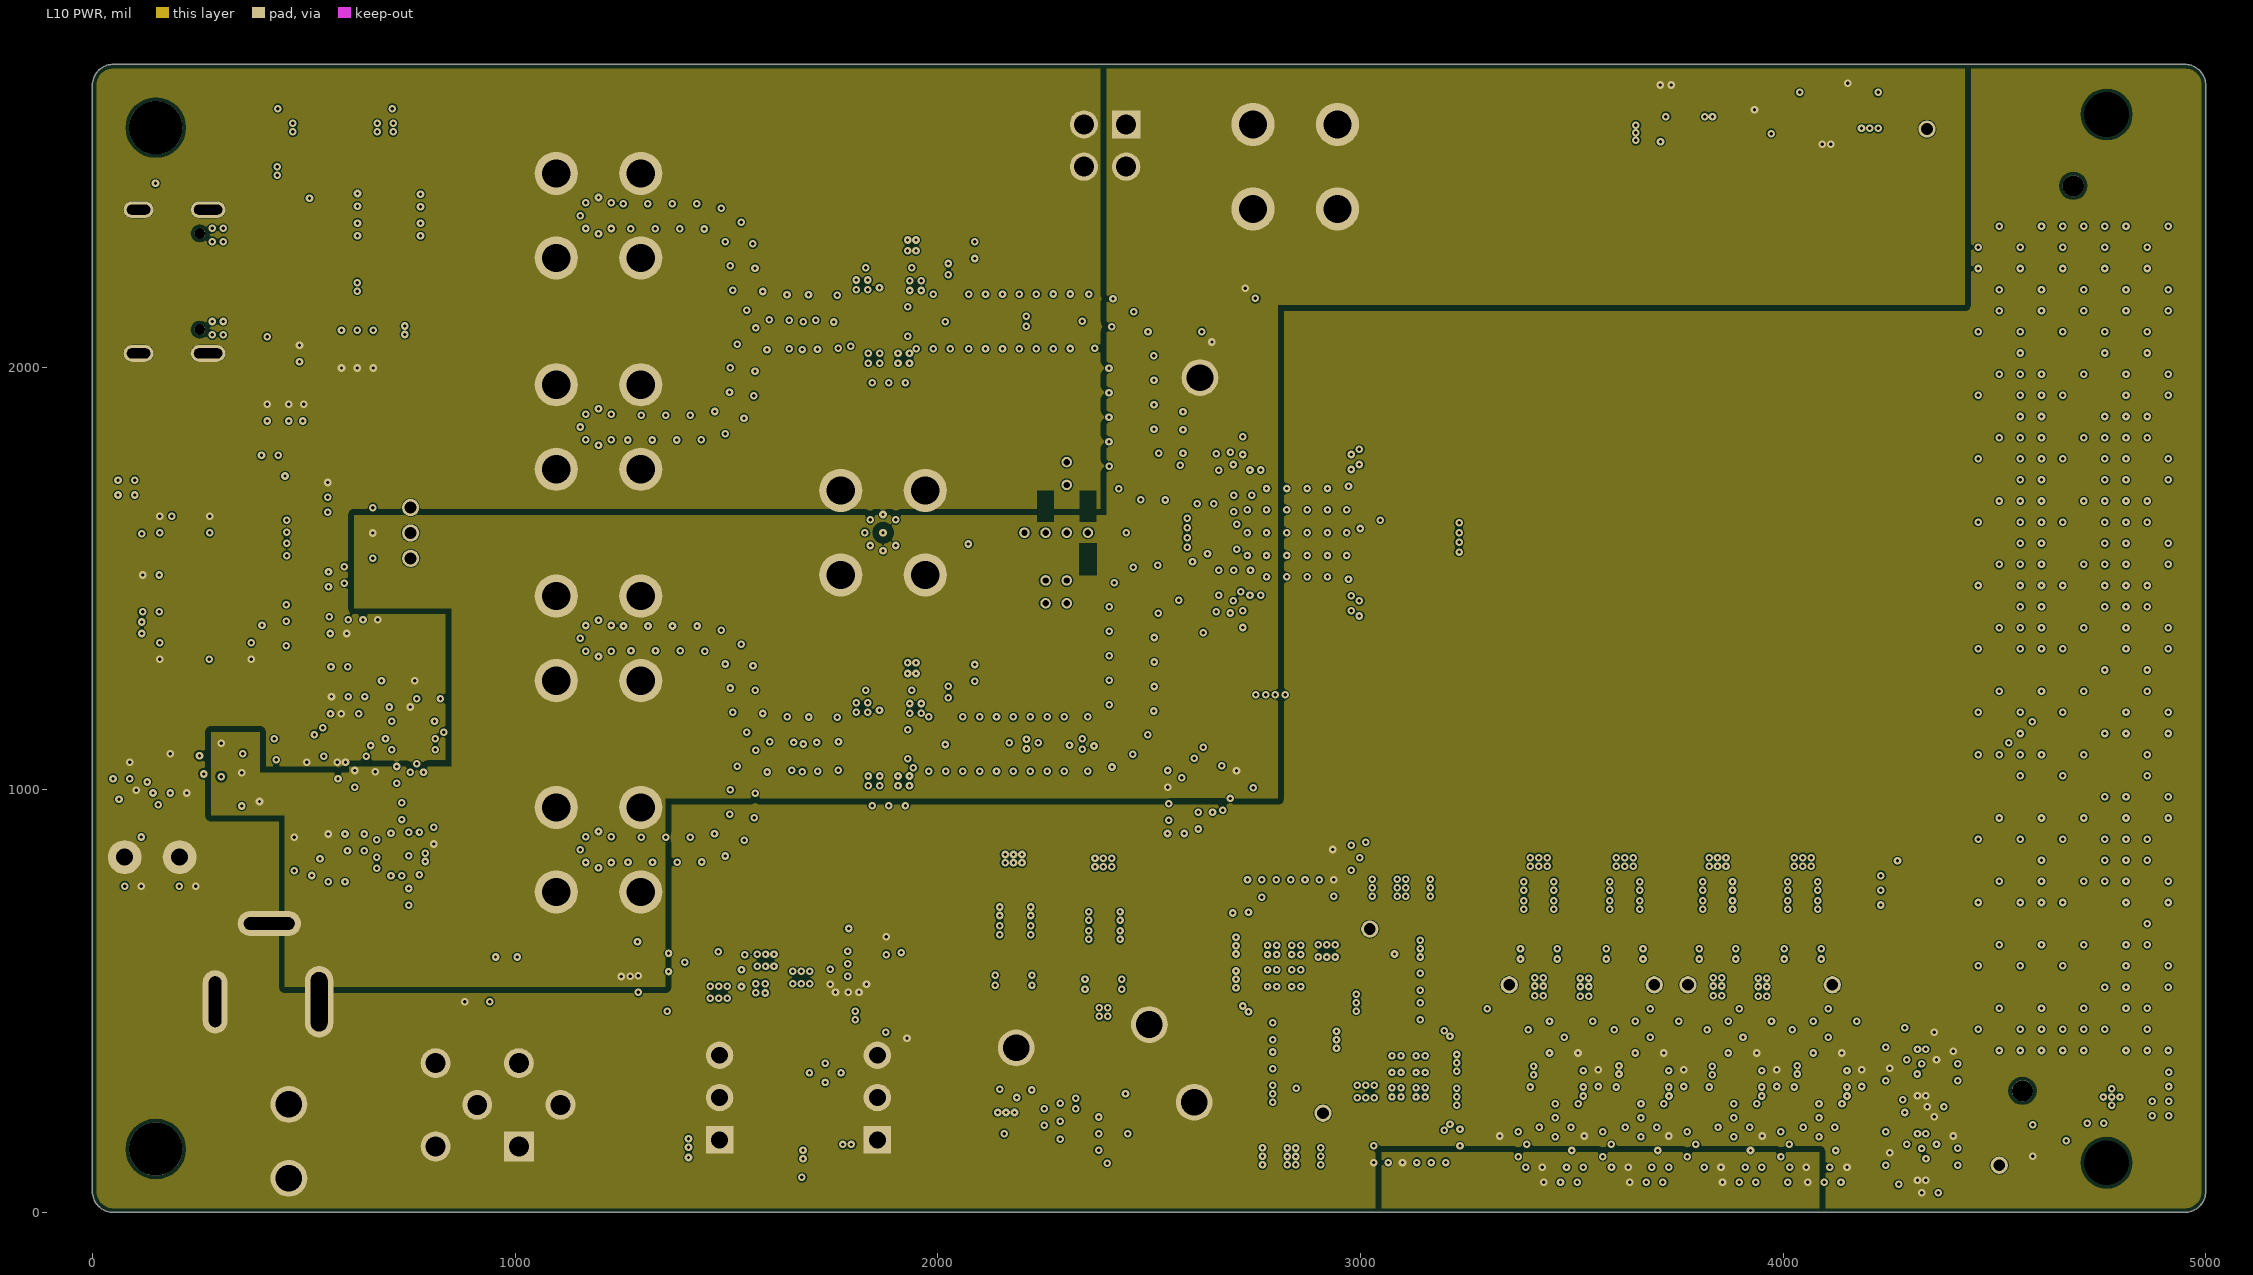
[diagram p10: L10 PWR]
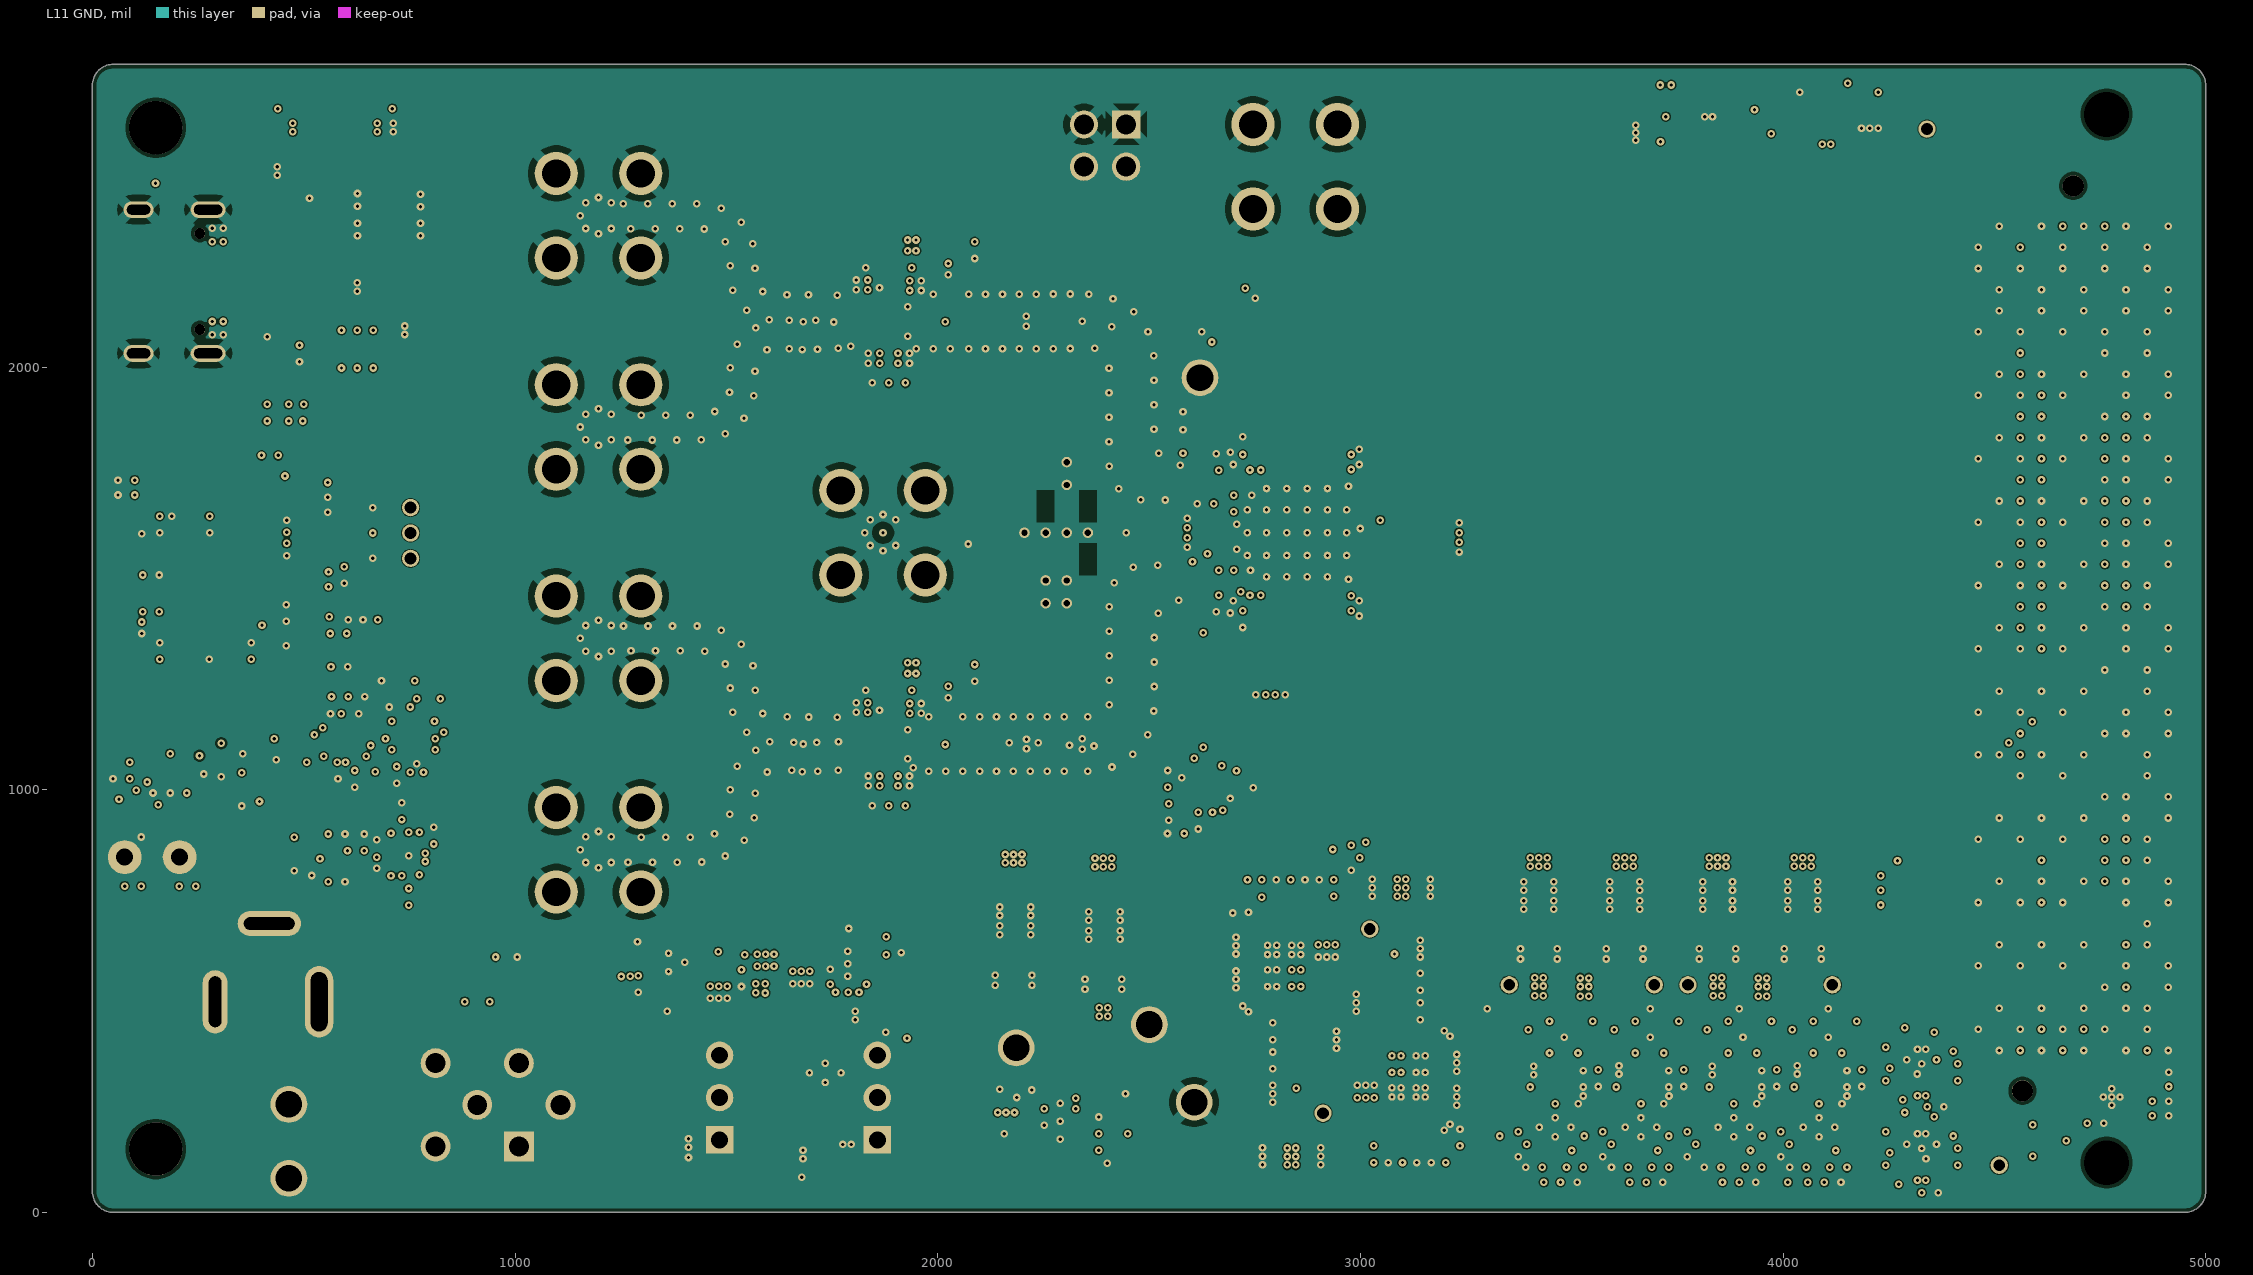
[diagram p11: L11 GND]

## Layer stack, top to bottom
Top Solder: solder mask 0.4, Solder Resist, Dk 3.5
Top Layer: signal copper 1.4
Dielectric 1: core 4.5, FR408HR, Dk 3.54
L2 GND: signal copper 1.4
Dielectric 3: prepreg 3.2, FR408HR, Dk 3.54
L3 SIG: signal copper 1.4
Dielectric 9: prepreg 3.2, FR408HR, Dk 3.54
L4 GND: signal copper 1.4
Dielectric 7: prepreg 3.2, FR408HR, Dk 3.54
L5 PWR: signal copper 1.4
Dielectric 5: prepreg 3.2, FR408HR, Dk 3.54
L6 GND: signal copper 1.4
Dielectric 11: prepreg 3.2, FR408HR, Dk 3.54
Dielectric1: prepreg 3.2, FR408HR, Dk 3.54
Dielectric 12: prepreg 3.2, FR408HR, Dk 3.54
L7 GND: signal copper 1.4
Dielectric 6: prepreg 3.2, FR408HR, Dk 3.54
L8 PWR: signal copper 1.4
Dielectric 8: prepreg 3.2, FR408HR, Dk 3.54
L9 GND: signal copper 1.4
Dielectric 10: prepreg 3.2, FR408HR, Dk 3.54
L10 PWR: signal copper 1.4
Dielectric 4: prepreg 3.2, FR408HR, Dk 3.54
L11 GND: signal copper 1.4
Dielectric 2: core 4.5, FR408HR, Dk 3.54
Bottom Layer: signal copper 1.4
Bottom Solder: solder mask 0.4, Solder Resist, Dk 3.5

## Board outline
0,50 0,2666.54 cw(c50,2666.54) 50,2716.54 4950,2716.54 cw(c4950,2666.54) 5000,2666.54 5000,50 cw(c4950,50) 4950,0 50,0 cw(c50,50)

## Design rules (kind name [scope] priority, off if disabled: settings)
AcuteAngle [All] p1: minimum=4.50000000000000E+0001 checktracksonly=TRUE
AssemblyTestPointUsage [All] p1: valid=2
BoardOutlineClearance BoardOutlineClearance_Poly_GND [OnCopper] p1: gap=25 ignorepadtopadclearanceinfootprint=FALSE except(10: Poly-OutlineEdge)
BoardOutlineClearance BoardOutlineClearance_Poly_GND_1 [OnCopper and IsPoly and InNet('GND')] p2: gap=25 ignorepadtopadclearanceinfootprint=FALSE except(10: Poly-OutlineEdge)
BoardOutlineClearance BoardOutlineClearance_MountingHoles_1 [OnCopper and InComponentClass('Mounting Holes')] p3: gap=39.37 ignorepadtopadclearanceinfootprint=FALSE
BoardOutlineClearance BoardOutlineClearance_Poly [OnCopper and IsPoly] p4: gap=25 ignorepadtopadclearanceinfootprint=FALSE
Clearance Clearance_Poly_GND [InPolygon and InNet('GND')] p1: gap=5 ignorepadtopadclearanceinfootprint=TRUE except(8: Arc-Hole Track-Hole SMDPad-Hole THPad-Hole Via-Hole Fill-Hole Poly-Hole Region-Hole Text-Hole; 10: SMDPad-Fill SMDPad-Poly SMDPad-Region THPad-Fill THPad-Poly THPad-Region; 15: Arc-Fill Arc-Poly Arc-Region Track-Fill Track-Poly Track-Region Fill-Fill Fill-Poly Fill-Region Poly-Poly Poly-Region Region-Region)
Clearance Clearance_Keepouts [((IsTrack Or IsArc) And Not InPoly) And IsFree and IsKeepOut vs ((IsTrack Or IsArc) And Not InPoly) And IsFree and IsKeepOut] p2: gap=0 ignorepadtopadclearanceinfootprint=FALSE
Clearance Clearance_Poly [InPolygon] p3: gap=5 ignorepadtopadclearanceinfootprint=TRUE except(8: Arc-Hole Track-Hole SMDPad-Hole THPad-Hole Via-Hole Fill-Hole Poly-Hole Region-Hole Text-Hole; 15: Fill-Fill Fill-Poly Fill-Region Poly-Poly Poly-Region Region-Region)
Clearance Clearance_FiducialMark [IsKeepOut and InComponentClass('FiducialMark') vs IsPad and InComponentClass('FiducialMark')] p4: gap=0 ignorepadtopadclearanceinfootprint=FALSE
Clearance [All vs not InAnyDifferentialPair] p5: gap=5 ignorepadtopadclearanceinfootprint=TRUE except(4: Arc-Arc Arc-Track Arc-SMDPad Arc-THPad Arc-Via Arc-Fill Arc-Poly Arc-Region Arc-Text Track-Track Track-SMDPad Track-THPad Track-Via Track-Fill Track-Poly Track-Region Track-Text; 8: Arc-Hole Track-Hole SMDPad-Hole THPad-Hole Via-Hole Fill-Hole Poly-Hole Region-Hole Text-Hole; 10: SMDPad-SMDPad THPad-Fill THPad-Poly THPad-Region)
ComponentClearance "ComponentClearance Part Overlap" [(InComponent('C105') OR InComponent('C112'))] p1: gap=0 collisioncheckmode=3 verticalgap=0 showdistances=FALSE
ComponentClearance ComponentClearance_ProbePoints_TH [HasFootprint('ProbePoint_TH_40mil')] p2: gap=10 collisioncheckmode=3 verticalgap=0 showdistances=FALSE donotcheckwithout3dbody=TRUE
ComponentClearance ComponentClearance_THtoSMT_NetTieVias [HasFootprint('Net-Tie-Via-8mil') vs IsSMTComponent] p3: gap=0 collisioncheckmode=3 verticalgap=0 showdistances=FALSE donotcheckwithout3dbody=TRUE
ComponentClearance ComponentClearance_MountingHoles_FiducialMarks [InComponentClass('Mounting Holes') vs InComponentClass('FiducialMark')] p4: gap=50 collisioncheckmode=3 verticalgap=10 showdistances=FALSE
ComponentClearance ComponentClearance_Shunt [InComponentClass('Header') vs InComponentClass('Shunt')] p5: gap=0 collisioncheckmode=3 verticalgap=0 showdistances=FALSE
ComponentClearance ComponentClearance_Logo [InComponentClass('Logo')] p6: gap=50 collisioncheckmode=3 verticalgap=10 showdistances=FALSE
ComponentClearance ComponentClearance_ScrewToNut [(HasFootprint('NY PMS 440 0025 PH')) vs (HasFootprint('Keystone_1902C'))] p7: gap=5 collisioncheckmode=3 verticalgap=10 showdistances=FALSE
ComponentClearance ComponentClearance_MountingHoles [InComponentClass('Mounting Holes')] p8: gap=200 collisioncheckmode=3 verticalgap=100000 showdistances=FALSE
ComponentClearance ComponentClearance_SmallPassives [HasFootprint('0201*') or HasFootprint('0402*') or HasFootprint('0508') or HasFootprint('0603*') or HasFootprint('0612') or HasFootprint('0805*') or HasFootprint('0815*') or HasFootprint('0830*') or HasFootprint('1206*') or HasFootprint('1210*') or HasFootprint('1808*') or HasFootprint('1812*') or HasFootprint('1825*') or HasFootprint('2010*') or HasFootprint('2220*') or HasFootprint('2225*') or HasFootprint('2512*') or HasFootprint('2728*') or HasFootprint('3518*') vs HasFootprint('0201*') or HasFootprint('0402*') or HasFootprint('0508') or HasFootprint('0603*') or HasFootprint('0612') or HasFootprint('0805*') or HasFootprint('0815*') or HasFootprint('0830*') or HasFootprint('1206*') or HasFootprint('1210*') or HasFootprint('1808*') or HasFootprint('1812*') or HasFootprint('1825*') or HasFootprint('2010*') or HasFootprint('2220*') or HasFootprint('2225*') or HasFootprint('2512*') or HasFootprint('2728*') or HasFootprint('3518*')] p9: gap=10 collisioncheckmode=3 verticalgap=10 showdistances=FALSE
ComponentClearance ComponentClearance_THtoSMT [IsThruComponent vs IsSMTComponent] p10: gap=10 collisioncheckmode=3 verticalgap=0 showdistances=FALSE
ComponentClearance ComponentClearance_THtoTH [IsThruComponent vs IsThruComponent] p11: gap=30 collisioncheckmode=3 verticalgap=30 showdistances=FALSE
ComponentClearance [All] p12: gap=10 collisioncheckmode=3 verticalgap=10 showdistances=FALSE
DiffPairsRouting [All] p1: maxlimit=15 minlimit=3 mostfreqgap=4 toplayer_minwidth=3 toplayer_maxwidth=15 toplayer_prefwidth=6 midlayer1_minwidth=3 midlayer1_maxwidth=15 midlayer1_prefwidth=5 midlayer2_minwidth=3 midlayer2_maxwidth=15 midlayer2_prefwidth=5 midlayer3_minwidth=3 midlayer3_maxwidth=15 midlayer3_prefwidth=5 midlayer4_minwidth=3 midlayer4_maxwidth=15 midlayer4_prefwidth=5 midlayer5_minwidth=3 midlayer5_maxwidth=15 midlayer5_prefwidth=5 midlayer6_minwidth=3 midlayer6_maxwidth=15 midlayer6_prefwidth=5 midlayer7_minwidth=3 midlayer7_maxwidth=15 midlayer7_prefwidth=5 midlayer8_minwidth=3 midlayer8_maxwidth=15 midlayer8_prefwidth=5 midlayer9_minwidth=3 midlayer9_maxwidth=15 midlayer9_prefwidth=5 midlayer10_minwidth=3 midlayer10_maxwidth=15 midlayer10_prefwidth=5 bottomlayer_minwidth=3 bottomlayer_maxwidth=15 bottomlayer_prefwidth=6 maxuncoupledlength=1000
FabricationTestPointUsage TestPointUsage [All] p1: valid=2 allowmultiple=FALSE
FabricationTestpoint Testpoint [All] p1: side=3 testpointundercomponent=TRUE minsize=40 maxsize=100 preferedsize=60 minholesize=0 maxholesize=40 preferedholesize=32 testpointgrid=1 allowsidetop=TRUE allowsidebottom=TRUE usegrid=TRUE gridtolerance=0.01
FanoutControl Fanout_LCC [IsLCC] p1: bgadir=Out bgaviamode=Centered fanoutstyle=Auto fanoutdirection=Alternating viagrid=1 // Fanout_LCC (Default Rule)
FanoutControl Fanout_BGA [IsBGA] p2: bgadir=Out bgaviamode=Centered fanoutstyle=Auto fanoutdirection=Alternating viagrid=1 // Fanout_BGA (Default Rule)
FanoutControl Fanout_Default [All] p4: bgadir=Out bgaviamode=Centered fanoutstyle=Auto fanoutdirection=Alternating viagrid=1 // Fanout_Default (Default Rule)
FanoutControl Fanout_Small [(CompPinCount < 5)] p5: bgadir=Out bgaviamode=Centered fanoutstyle=Auto fanoutdirection=OutThenIn viagrid=1 // Fanout_Small (Default Rule)
HoleSize [All] p1: absolutevalues=TRUE maxlimit=251 minlimit=7.87 maxpercent=80.000 minpercent=20.000
HoleToHoleClearance HoleToHoleClearance_MarkiBalun [(InComponent('t4') OR InComponent('t5'))] p1: gap=7 allowstackedmicrovias=TRUE
HoleToHoleClearance [All] p2: gap=9 allowstackedmicrovias=TRUE
MatchedLengths LVDS-Interpair [InNetClass('SERDES')] p1: tolerance=20 checknetsindiffpair=FALSE checkdiffpairvsdiffpair=TRUE checkxsignals=TRUE checkothers=TRUE
MatchedLengths [InDifferentialPair('FMC_DOUT0')] p2: tolerance=2 checknetsindiffpair=FALSE checkdiffpairvsdiffpair=TRUE checkxsignals=TRUE checkothers=TRUE
MinimumAnnularRing MinimumAnnularRing_ThermalPadVias [IsVia and InAnyComponent] p1: minimumring=0
MinimumAnnularRing [All] p2: minimumring=0
MinimumSolderMaskSliver MinimumSolderMaskSliver_Baluns [InComponent('T4')or InComponent('T5')] p1: minsoldermaskwidth=0
MinimumSolderMaskSliver MinimumSolderMaskSliver_Logo [InComponentClass('Logo') vs InComponentClass('Logo')] p2: minsoldermaskwidth=0.7
MinimumSolderMaskSliver [All] p3: minsoldermaskwidth=3
NetAntennae [Not((InNetClass('PWR1') or InNetClass('PWR2') or InNetClass('PWR3') or InNetClass('PWR4')) and ViaDiameter = 20)] p1: netantennaetolerance=0
PlaneConnect [All] p1: planeconnectstyle=Relief reliefexpansion=10 reliefentries=4 reliefconductorwidth=10 reliefairgap=10
PolygonConnect "Thermal Pads" [IsPolygon vs IsPad and HoleSize <= 41] p1: connectstyle=Direct reliefconductorwidth=10 reliefentries=4 polygonreliefangle="90 Angle" airgapwidth=10
PolygonConnect [All] p2: thpad.connectstyle=Relief thpad.reliefconductorwidth=25 thpad.reliefentries=4 thpad.polygonreliefangle="45 Angle" thpad.airgapwidth=15 smdpad.connectstyle=Direct smdpad.reliefconductorwidth=10 smdpad.reliefentries=4 smdpad.polygonreliefangle="90 Angle" smdpad.airgapwidth=10 via.connectstyle=Direct via.reliefconductorwidth=10 via.reliefentries=4 via.polygonreliefangle="90 Angle" via.airgapwidth=10
RoutingVias ThermalPadVias [IsVia and InAnyComponent] p1: holewidth=7.87 width=19.68 viastyle="Through Hole" minholewidth=6 minwidth=16 maxholewidth=65 maxwidth=65
RoutingVias [All] p2: holewidth=16 width=34 viastyle="Through Hole" minholewidth=6 minwidth=16 maxholewidth=40 maxwidth=65
SilkToBoardRegionClearance [Not ((IsComment or IsDesignator) And (Hide <> 'False')) and not InRegion(1000,500,4000,800)] p1:
SilkToSilkClearance SilkToSilkClearance_Pb-FreeLogo [(HasFootprint('Pb-Free_Overlay_Medium') OR HasFootprint('Pb-Free_Overlay_Small')) vs (HasFootprint('Pb-Free_Overlay_Medium') OR HasFootprint('Pb-Free_Overlay_Small'))] p1: silktosilkclearance=0
SilkToSilkClearance [All] p2: silktosilkclearance=0
SilkToSolderMaskClearance SilkToComponentPadClearance [(IsPad or IsFill or IsRegion) and InAnycomponent] p1: minsilkscreentomaskgap=0 clearancetoexposedcopper=TRUE
SilkToSolderMaskClearance "Silk to Solder Mask Opening" [All] p2: minsilkscreentomaskgap=0 clearancetoexposedcopper=FALSE
SolderMaskExpansion [All] p1: expansion=1.97 istentingtop=FALSE
SupplyNets "Schematic Supply Nets_9" [InNet('-1p1V_LMH')] p1: voltage=0.000
SupplyNets "Schematic Supply Nets_8" [InNet('5V')] p2: voltage=0.000
SupplyNets "Schematic Supply Nets_17" [InNet('12V_FMC')] p3: voltage=0.000
SupplyNets "Schematic Supply Nets_16" [InNet('2p3V_LDO')] p4: voltage=0.000
SupplyNets "Schematic Supply Nets_15" [InNet('GND')] p5: voltage=0.000
SupplyNets "Schematic Supply Nets_14" [InNet('3p9V_LMH')] p6: voltage=0.000
SupplyNets "Schematic Supply Nets_13" [InNet('1p8V_Utility')] p7: voltage=0.000
SupplyNets "Schematic Supply Nets_12" [InNet('4p3V_LDO')] p8: voltage=0.000
SupplyNets "Schematic Supply Nets_10" [InNet('AVDD18')] p9: voltage=0.000
SupplyNets "Schematic Supply Nets_7" [InNet('3p3V_AUX')] p10: voltage=0.000
SupplyNets "Schematic Supply Nets_6" [InNet('3p3V_Utility')] p11: voltage=0.000
SupplyNets "Schematic Supply Nets_5" [InNet('DVDD18')] p12: voltage=0.000
SupplyNets "Schematic Supply Nets_4" [InNet('DVDD12')] p13: voltage=0.000
SupplyNets "Schematic Supply Nets_3" [InNet('AVDD12')] p14: voltage=0.000
SupplyNets "Schematic Supply Nets_2" [InNet('VADJ')] p15: voltage=0.000
SupplyNets "Schematic Supply Nets_1" [InNet('3p3V_EEPROM')] p16: voltage=0.000
SupplyNets "Schematic Supply Nets" [InNet('MainPwr')] p17: voltage=0.000
UnRoutedNet [All] p1: checkbadconnections=TRUE
Width Width_InPolygon [InNet('GND') OR InNet('3p3V') OR InNet('1p8V') OR InNet('LMX_2p5V')] p1: maxlimit=10000 minlimit=0 preferedwidth=0 checkconnectedcopper=TRUE
Width [All] p2: maxlimit=100 minlimit=4 preferedwidth=5 toplayer_prefwidth=9.65 bottomlayer_prefwidth=9.65 minimp=50.000000 maximp=50.000000 favimp=50.000000 checkconnectedcopper=TRUE
12 further rules are at their usual default settings.

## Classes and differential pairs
component class "I2C SPI Mux": C183 C184 PP12 PP13 PP14 R245 R246 R247 R248 R249 R250 R251 R252 R253 R254 R255 R256 SW3 TP5 TP6 U32 U33
component class "FMC Sections 1-7 ": C164 D6 J9 R180 R181 R182 R183 R184 R185 R186 R187 R191 U25
component class "Comms Level Shift": C185 C186 C187 C188 C189 C190 NT1 NT2 R188 R257 R258 R259 R260 R261 R262 R263 R264 R266 R267 U34 U35 U36
component class "LMH Power LDO": C50 C51 C52 C53 C54 C55 C71 C72 C77 C78 D5 FC5 FC6 R53 R54 R55 R56 R57 R58 R59 R73 R74 R75 TP8 TP9 U16
component class "FTDI USB Input": C166 C167 C168 C169 C170 C171 C172 C173 C174 C175 C176 C177 C178 C180 C181 C182 D7 FB11 FB12 J10 R178 R179 R189 R190 R209 R210 R211 R212 R213 R214 R215 R216 R217 R218 R219 R220 R221 R222 R224 R225 R227 R229 R240 R241 R242 R243 R244 U27 U28 U29 U31 Y1
component class "ADC Analog Input": C92 C96 C99 C101 C104 C105 C106 C107 C108 C109 C111 C115 C118 C120 C122 C123 C124 J6 L1 L2 L3 L4 R129 R130 R131 R132 R133 R134 R135 R136 R137 R138 R139 T2 TP4 U1
component class "ADC IO": C80 C81 C82 C83 C84 C85 C86 C87 C88 C89 C90 J2 J3 PP11 R82 R83 R84 R85 R86 R87 R88 R89 R90 R91 R92 R93 R94 R95 R96 R97 R98 R99 R100 R101 R102 R103 R104 R105 R106 R107 R108 R109 R111 R112 R113 R114 R115 R117 R118 R119 R120 R121 R122 R123 R124 R125 R126 R127 R128 SW2 U20 U42
component class "LMH Power DC-DC": C59 C60 C61 C62 C63 C64 C65 C66 FB8 J12 PP8 R60 R64 R65 R66 R67 R68 R69 R70 R77 U17 U45
net class GenPwr: 1p8V_Utility 3p3V_Utility
component class "ADC Power DC-DC": C14 C15 C16 C17 C18 C19 C20 C21 C56 C57 C58 C67 FB2 PP2 R13 R14 R15 R16 R17 R18 R61 R62 R78 R273 R274 R275 U7 U18 U19 U41
net class ADC_Power: 2p3V_LDO 3p9V_LMH 4p3V_LDO -1p1V_LMH AVDD12 AVDD18 DVDD12 DVDD18
net class Power: 1p8V_Utility 2p3V_LDO 3p3V_Utility 3p9V_LMH 4p3V_LDO -1p1V_LMH AVDD12 AVDD18 DVDD12 DVDD18 MainPwr
net class SERDES: FMC_DCLK_n FMC_DCLK_p FMC_DOUT0_n FMC_DOUT0_p FMC_DOUT1_n FMC_DOUT1_p FMC_DOUT2_n FMC_DOUT2_p FMC_DOUT3_n FMC_DOUT3_p FMC_DOUT4_n FMC_DOUT4_p FMC_DOUT5_n FMC_DOUT5_p FMC_DOUT6_n FMC_DOUT6_p FMC_DOUT7_n FMC_DOUT7_p FMC_DOUT8_n FMC_DOUT8_p FMC_DOUT9_n FMC_DOUT9_p FMC_DOUT10_n FMC_DOUT10_p FMC_DOUT11_n FMC_DOUT11_p FMC_DOUT12_n FMC_DOUT12_p FMC_DOUT13_n FMC_DOUT13_p FMC_DOUT14_n FMC_DOUT14_p FMC_DOUT15_n FMC_DOUT15_p
component class "EVM Power": C1 C2 C3 C4 C5 C6 C7 C8 C9 C10 C11 C12 C13 D1 D2 D3 D4 F1 F2 FB1 J1 PP1 Q1 Q2 R1 R2 R3 R4 R5 R6 R7 R8 R9 R10 R11 R12 SW1 TP1 TP2 TP3 U2 U3 U4 U5 U6
component class Amplifier: C126 C127 C128 C129 C130 C131 C132 C133 C134 C135 C136 C137 C138 C139 C140 C141 C142 C144 C145 C146 C147 C148 C149 C150 C151 C152 C153 C154 C155 C156 C157 C158 C159 C160 C161 C163 J4 J5 J7 J8 J12 R140 R141 R142 R143 R144 R145 R146 R147 R148 R149 R150 R151 R152 R153 R154 R155 R156 R157 R158 R159 R160 R161 R162 R163 R164 R165 R166 R167 R168 R169 R170 R171 R172 R173 R174 R175 R176 R177 U21 U22 U23 U24
component class "ADC Power": C22 C23 C24 C25 C26 C27 C28 C29 C30 C31 C32 C33 C34 C35 C36 C37 C38 C39 C40 C41 C42 C43 C44 C45 C46 C47 C48 C49 FB3 FB4 FB5 FB6 FC1 FC2 FC3 FC4 PP3 PP4 PP5 PP6 R19 R20 R21 R22 R23 R24 R25 R26 R27 R28 R29 R30 R31 R32 R33 R34 R35 R36 R37 R38 R39 R40 R41 R42 R43 R44 R45 R46 R47 R48 R49 R50 R51 R52 R63 R71 R72 R76 R81 R110 R116 R272 U8 U9 U10 U11 U12 U13 U14 U15 U39 U40 U43 U44
component class Hardware: !PCB1 FID1 FID2 FID3 H5 H6 LBL1 Logo1 Logo2 Logo3 Logo4 LOGO5 Logo6 ZZ1 ZZ2 ZZ3 ZZ4
component class AssemblyNote: ZZ1 ZZ2 ZZ3 ZZ4
component class "FMC Sections 8-14": C165 R79 R80 R192 R193 R194 R195 R196 R197 R198 R199 R200 R201 R204 R207 R208 U26
differential pair CLK_IN: +CLK_IN_P -CLK_IN_N
differential pair CHB_IN: +CHB_IN_P -CHB_IN_N
differential pair CHA_IN: +CHA_IN_P -CHA_IN_N
differential pair FMC_DOUT0: +FMC_DOUT0_p -FMC_DOUT0_n
differential pair FMC_DOUT15: +FMC_DOUT15_p -FMC_DOUT15_n
differential pair FMC_DOUT14: +FMC_DOUT14_p -FMC_DOUT14_n
differential pair FMC_DOUT13: +FMC_DOUT13_p -FMC_DOUT13_n
differential pair FMC_DOUT12: +FMC_DOUT12_p -FMC_DOUT12_n
differential pair FMC_DOUT11: +FMC_DOUT11_p -FMC_DOUT11_n
differential pair FMC_DOUT10: +FMC_DOUT10_p -FMC_DOUT10_n
differential pair FMC_DOUT9: +FMC_DOUT9_p -FMC_DOUT9_n
differential pair FMC_DOUT8: +FMC_DOUT8_p -FMC_DOUT8_n
differential pair FMC_DOUT7: +FMC_DOUT7_p -FMC_DOUT7_n
differential pair FMC_DOUT6: +FMC_DOUT6_p -FMC_DOUT6_n
differential pair FMC_DOUT5: +FMC_DOUT5_p -FMC_DOUT5_n
differential pair FMC_DOUT4: +FMC_DOUT4_p -FMC_DOUT4_n
differential pair FMC_DOUT3: +FMC_DOUT3_p -FMC_DOUT3_n
differential pair FMC_DOUT2: +FMC_DOUT2_p -FMC_DOUT2_n
differential pair FMC_DOUT1: +FMC_DOUT1_p -FMC_DOUT1_n
differential pair FMC_DCLK: +FMC_DCLK_p -FMC_DCLK_n
differential pair DOUT15: +DOUT15_p -DOUT15_n
differential pair DOUT14: +DOUT14_p -DOUT14_n
differential pair DOUT13: +DOUT13_p -DOUT13_n
differential pair DOUT12: +DOUT12_p -DOUT12_n
differential pair DOUT11: +DOUT11_p -DOUT11_n
differential pair DOUT10: +DOUT10_p -DOUT10_n
differential pair DOUT9: +DOUT9_p -DOUT9_n
differential pair DOUT8: +DOUT8_p -DOUT8_n
differential pair DOUT7: +DOUT7_p -DOUT7_n
differential pair DOUT6: +DOUT6_p -DOUT6_n
differential pair DOUT5: +DOUT5_p -DOUT5_n
differential pair DOUT4: +DOUT4_p -DOUT4_n
differential pair DOUT3: +DOUT3_p -DOUT3_n
differential pair DOUT2: +DOUT2_p -DOUT2_n
differential pair DOUT1: +DOUT1_p -DOUT1_n
differential pair DOUT0: +DOUT0_p -DOUT0_n
differential pair DCLK: +DCLK_p -DCLK_n

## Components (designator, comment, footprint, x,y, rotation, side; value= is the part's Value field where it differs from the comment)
C1 "0402ZD106MAT2A" 0402L_cap#1 1535.7,554.18 r90 top value="10 uF"
C2 "06035C105KAT2A" 0603L_cap#1 1357.02,285.87 r270 bottom value="1 uF"
C3 "CGA3E2X7R1H102K080AA" 0603L_cap#1 1689.46,137.77 r0 bottom value="0.001 uF"
C4 "CGA3E2X7R1H102K080AA" 0603L_cap#1 1785.23,169.31 r90 bottom value="0.001 uF"
C5 "C1005X5R1E104K050BC" 0402L_cap#1 4337.64,96.01 r270 bottom value="0.1 uF"
C6 "C1005X5R1E104K050BC" 0402L_cap#1 4347.49,46.52 r180 bottom value="0.1 uF"
C7 "08053D106KAT4A" 0805L_cap#1 1676.98,555.78 r90 top value="10 uF"
C8 "08053D106KAT4A" 0805L_cap#1 1481.94,520.97 r90 bottom value="10 uF"
C9 "C1005X5R1A475K050BE" 0402L_cap#1 1291.77,540.4 r90 bottom value="4.7 uF"
C10 "C1005X5R1A475K050BE" 0402L_cap#1 1787.87,540.4 r270 bottom value="4.7 uF"
C11 "C1005X5R1E104K050BC" 0402L_cap#1 4360.9,250.04 r180 top value="0.1 uF"
C12 "C1005X5R1E104K050BC" 0402L_cap#1 4317.96,296.01 r270 bottom value="0.1 uF"
C13 "04025C332K4T2A" 0402L_cap#2 1808.83,671.71 r0 top value="3300 pF"
C14 "08053D106KAT4A" 0805L_cap#1 3011.22,286.03 r270 bottom value="10 uF"
C15 "04023C222JAT2A" 0402L_cap#1 2992.94,286.03 r270 top value="2200 pF"
C16 "0805ZD226KAT2A" 0805L_cap#1 3126.78,476.31 r180 top value="22 uF"
C17 "0805ZD226KAT2A" 0805L_cap#1 3002.77,496.31 r0 top value="22 uF"
C18 "0805ZD226KAT2A" 0805L_cap#1 3126.78,545.62 r180 top value="22 uF"
C19 "0805ZD226KAT2A" 0805L_cap#1 3153.15,768 r180 top value="22 uF"
C20 "0805ZD226KAT2A" 0805L_cap#1 3040.79,768 r0 top value="22 uF"
C21 "CGA2B2X7R1E223K050BA" 0402L_cap#1 3065.64,137.75 r90 top value="0.022 uF"
C22 "C1005X5R1E104K050BC" 0402L_cap#2 3765.24,317.81 r90 bottom value="0.1 uF"
C23 "C1005X5R1E104K050BC" 0402L_cap#1 3613.8,106.52 r0 top value="0.1 uF"
C24 "0402ZD106MAT2A" 0402L_cap#1 3624.38,337.49 r0 top value="10 uF"
C25 "C1005X5R1E105K050BC" 0402L_cap#2 3665.88,481.66 r180 top value="1 uF"
C26 "0402ZD106MAT2A" 0402L_cap#1 3601.57,727.59 r0 top value="10 uF"
C27 "0402ZD106MAT2A" 0402L_cap#1 3601.57,772.59 r0 top value="10 uF"
C28 "C1005X5R1E105K050BC" 0402L_cap#1 3710.23,296.76 r180 top value="1 uF"
C29 "C1005X5R1E104K050BC" 0402L_cap#2 3562.31,317.81 r90 bottom value="0.1 uF"
C30 "C1005X5R1E104K050BC" 0402L_cap#1 3410.87,106.52 r0 top value="0.1 uF"
C31 "0402ZD106MAT2A" 0402L_cap#1 3421.47,335.73 r0 top value="10 uF"
C32 "C1005X5R1E105K050BC" 0402L_cap#1 3319.73,481.63 r0 top value="1 uF"
C33 "0402ZD106MAT2A" 0402L_cap#1 3398.64,727.59 r0 top value="10 uF"
C34 "0402ZD106MAT2A" 0402L_cap#1 3398.64,772.59 r0 top value="10 uF"
C35 "C1005X5R1E105K050BC" 0402L_cap#1 3507.3,296.76 r180 top value="1 uF"
C36 "C1005X5R1E104K050BC" 0402L_cap#2 4186.55,317.81 r90 bottom value="0.1 uF"
C37 "C1005X5R1E104K050BC" 0402L_cap#1 4035.11,106.52 r0 top value="0.1 uF"
C38 "0402ZD106MAT2A" 0402L_cap#1 4045.69,337.49 r0 top value="10 uF"
C39 "C1005X5R1E105K050BC" 0402L_cap#1 4087.34,481.63 r180 top value="1 uF"
C40 "0402ZD106MAT2A" 0402L_cap#1 4022.88,727.59 r0 top value="10 uF"
C41 "0402ZD106MAT2A" 0402L_cap#1 4022.88,772.59 r0 top value="10 uF"
C42 "C1005X5R1E105K050BC" 0402L_cap#1 4131.54,296.76 r180 top value="1 uF"
C43 "C1005X5R1E104K050BC" 0402L_cap#2 3985,317.81 r90 bottom value="0.1 uF"
C44 "C1005X5R1E104K050BC" 0402L_cap#1 3833.56,106.52 r0 top value="0.1 uF"
C45 "0402ZD106MAT2A" 0402L_cap#1 3844.16,335.73 r0 top value="10 uF"
C46 "C1005X5R1E105K050BC" 0402L_cap#2 3876.44,481.6 r180 top value="1 uF"
C47 "0402ZD106MAT2A" 0402L_cap#1 3821.32,727.59 r0 top value="10 uF"
C48 "0402ZD106MAT2A" 0402L_cap#1 3821.32,772.59 r0 top value="10 uF"
C49 "C1005X5R1E105K050BC" 0402L_cap#1 3929.98,296.76 r180 top value="1 uF"
C50 "0603ZD106KAT2A" 0603L_cap#2 2146.65,263.98 r270 top value="10 uF"
C51 "C1005X5R1A225K050BC" 0402L_cap#2 2187.15,252.17 r270 top value="2.2 uF"
C52 "GRM033R61A105ME44D" 0201_cap#1 2356.95,215.75 r270 top value="1 uF"
C53 "0603ZD106KAT2A" 0603L_cap#2 2318.7,72.31 r180 top value="10 uF"
C54 "0603ZD106KAT2A" 0603L_cap#2 2184.59,186.23 r0 top value="10 uF"
C55 "0603ZD106KAT2A" 0603L_cap#2 2416.69,280.81 r180 top value="10 uF"
C56 "GMC21X5R107M6R3NT" 0805L_cap#2 644.82,2394.17 r0 bottom value="100 uF"
C57 "GMC21X5R107M6R3NT" 0805L_cap#2 758.87,2324.17 r180 bottom value="100 uF"
C58 "GMC21X5R107M6R3NT" 0805L_cap#2 644.82,2324.17 r0 bottom value="100 uF"
C59 "08053D106KAT4A" 0805L_cap#1 2920.81,619.14 r90 bottom value="10 uF"
C60 "04023C222JAT2A" 0402L_cap#1 2940.69,619.14 r90 top value="2200 pF"
C61 "0805ZD226KAT2A" 0805L_cap#1 2806.86,428.86 r0 top value="22 uF"
C62 "0805ZD226KAT2A" 0805L_cap#1 2930.87,408.86 r180 top value="22 uF"
C63 "0805ZD226KAT2A" 0805L_cap#1 2806.86,359.55 r0 top value="22 uF"
C64 "0805ZD226KAT2A" 0805L_cap#1 2780.87,132.92 r0 top value="22 uF"
C65 "0805ZD226KAT2A" 0805L_cap#1 2893.23,132.92 r180 top value="22 uF"
C66 "CGA2B2X7R1E223K050BA" 0402L_cap#1 2903,767.42 r270 top value="0.022 uF"
C67 "GMC21X5R107M6R3NT" 0805L_cap#2 758.87,2394.17 r180 bottom value="100 uF"
C71 "0402ZD106MAT2A" 0402L_cap#1 2158.22,712.41 r0 top value="10 uF"
C72 "0402ZD106MAT2A" 0402L_cap#1 2158.22,667.65 r0 top value="10 uF"
C77 "0402ZD106MAT2A" 0402L_cap#1 2369.44,656.04 r0 top value="10 uF"
C78 "0402ZD106MAT2A" 0402L_cap#1 2369.44,701.04 r0 top value="10 uF"
C80 "C1005X5R1E105K050BC" 0402L_cap#1 2722.05,1403.55 r90 bottom value="1 uF"
C81 "C1005X5R1E104K050BC" 0402L_cap#1 2722.05,1815.99 r270 bottom value="0.1 uF"
C82 "C1005X5R1E104K050BC" 0402L_cap#1 2720.27,1657.48 r180 bottom value="0.1 uF"
C83 "C1005X5R1E105K050BC" 0402L_cap#1 2971.95,1478.54 r270 bottom value="1 uF"
C84 "C1005X5R1E104K050BC" 0402L_cap#1 2971.95,1738 r90 bottom value="0.1 uF"
C85 "C1005X5R1E105K050BC" 0402L_cap#1 2723.27,1696.85 r180 bottom value="1 uF"
C86 "C1005X5R1E104K050BC" 0402L_cap#1 2720.27,1519.69 r180 bottom value="0.1 uF"
C87 "C1005X5R1E105K050BC" 0402L_cap#1 2658.96,1440.95 r90 bottom value="1 uF"
C88 "C1005X5R1E104K050BC" 0402L_cap#1 2658.96,1775.59 r270 bottom value="0.1 uF"
C89 "C1005X5R1E104K050BC" 0402L_cap#1 3027.36,1637.8 r0 bottom value="0.1 uF"
C90 "C1005X5R1E104K050BC" 0402L_cap#1 4147.35,2553.92 r225 bottom value="0.1 uF"
C92 "GRM033Z71C104KE14D" 0201_cap#1 2243.02,2141.82 r0 top value="0.1 uF"
C96 "02015J1R0PBSTR" 0201_cap#1 2342.09,2131.79 r90 top value="1 pF"
C99 "02015J1R0PBSTR" 0201_cap#1 2342.1,2085.32 r90 top value="1 pF"
C101 "GRM033Z71C104KE14D" 0201_cap#1 2243.02,2074.72 r180 top value="0.1 uF"
C104 "GRM033Z71C104KE14D" 0201_cap#2 2110.03,1630.17 r90 bottom value="0.1 uF"
C105 "GRM033Z71C104KE14D" 0201_cap#2 2457.86,1654.1 r0 bottom value="0.1 uF"
C106 "GRM033Z71C104KE14D" 0201_cap#1 2624.01,1619.83 r0 top value="0.1 uF"
C107 "GRM033Z71C104KE14D" 0201_cap#1 2624.01,1596.71 r0 top value="0.1 uF"
C108 "GRM033Z71C104KE14D" 0201_cap#2 2457.86,1562.44 r0 bottom value="0.1 uF"
C109 "GRM033Z71C104KE14D" 0201_cap#2 2434.86,1608.27 r180 bottom value="0.1 uF"
C111 "GRM033Z71C104KE14D" 0201_cap#1 2243.02,1141.82 r180 top value="0.1 uF"
C115 "02015J1R0PBSTR" 0201_cap#1 2342.09,1131.79 r90 top value="1 pF"
C118 "02015J1R0PBSTR" 0201_cap#1 2342.1,1084.75 r90 top value="1 pF"
C120 "GRM033Z71C104KE14D" 0201_cap#1 2243.02,1074.72 r0 top value="0.1 uF"
C122 "0402ZD106MAT2A" 0402L_cap#1 2600,1851.39 r0 bottom value="10 uF"
C123 "C1005X5R1E104K050BC" 0402L_cap#1 2600,1893.97 r0 bottom value="0.1 uF"
C124 "C1005X5R1E104K050BC" 0402L_cap#1 2633.28,1677.17 r0 bottom value="0.1 uF"
C126 "CGA1A2X7R1A103K030BA" 0201_cap#1 1944.96,2181.15 r180 top value="0.01 uF"
C127 "CGA1A2X7R1A103K030BA" 0201_cap#1 1917.12,2032.56 r180 top value="0.01 uF"
C128 "0201ZC222KAT2A" 0201_cap#1 1917.12,2009.56 r180 top value="2200 pF"
C129 "0201ZC222KAT2A" 0201_cap#1 1944.96,2204.15 r180 top value="2200 pF"
C130 "CGA1A2X7R1A103K030BA" 0201_cap#1 1851.38,2009.56 r0 top value="0.01 uF"
C131 "CGA1A2X7R1A103K030BA" 0201_cap#1 1823.54,2183.12 r0 top value="0.01 uF"
C132 "0201ZC222KAT2A" 0201_cap#1 1851.38,2032.56 r0 top value="2200 pF"
C133 "0201ZC222KAT2A" 0201_cap#1 1823.54,2206.12 r0 top value="2200 pF"
C134 "GRM033Z71C104KE14D" 0201_cap#1 1714.85,2073.19 r0 top value="0.1 uF"
C135 "GJM0335C1E2R0WB01D" 0201_cap#1 2209.59,2130.79 r90 top value="2 pF"
C136 "GJM0335C1ER70BB01J" 0201_cap#1 2041.3,2107.96 r90 top value="0.7 pF"
C137 "GJM0335C1E6R6CB01D" 0201_cap#1 2136.16,2109.98 r90 top value="6.6 pF"
C138 "GJM0335C1E2R0WB01D" 0201_cap#1 2209.48,2085.7 r90 top value="2 pF"
C139 "GRM033Z71C104KE14D" 0201_cap#1 1714.85,2140.59 r0 top value="0.1 uF"
C140 "CGA1A2X7R1A103K030BA" 0201_cap#1 1873.23,2183.12 r0 top value="0.01 uF"
C141 "C1005X5R1E105K050BC" 0402L_cap#2 1981.93,2366.3 r180 top value="1 uF"
C142 "C1005X5R1E105K050BC" 0402L_cap#2 2087.28,2276.61 r270 top value="1 uF"
C144 "CGA1A2X7R1A103K030BA" 0201_cap#1 2025.23,2234.09 r90 top value="0.01 uF"
C145 "CGA1A2X7R1A103K030BA" 0201_cap#1 1917.12,1032.56 r180 top value="0.01 uF"
C146 "CGA1A2X7R1A103K030BA" 0201_cap#1 1944.96,1181.15 r180 top value="0.01 uF"
C147 "0201ZC222KAT2A" 0201_cap#1 1944.96,1204.15 r180 top value="2200 pF"
C148 "0201ZC222KAT2A" 0201_cap#1 1917.12,1009.56 r180 top value="2200 pF"
C149 "CGA1A2X7R1A103K030BA" 0201_cap#1 1823.54,1206.12 r0 top value="0.01 uF"
C150 "CGA1A2X7R1A103K030BA" 0201_cap#1 1851.38,1032.56 r0 top value="0.01 uF"
C151 "0201ZC222KAT2A" 0201_cap#1 1823.54,1183.12 r0 top value="2200 pF"
C152 "0201ZC222KAT2A" 0201_cap#1 1851.38,1009.56 r0 top value="2200 pF"
C153 "GRM033Z71C104KE14D" 0201_cap#1 1715.25,1074.57 r0 top value="0.1 uF"
C154 "GJM0335C1E2R0WB01D" 0201_cap#1 2210,1130.91 r90 top value="2 pF"
C155 "GJM0335C1ER70BB01J" 0201_cap#1 2041.38,1107.71 r90 top value="0.7 pF"
C156 "GJM0335C1E6R6CB01D" 0201_cap#1 2136.3,1108.5 r90 top value="6.6 pF"
C157 "GJM0335C1E2R0WB01D" 0201_cap#1 2210,1085.63 r90 top value="2 pF"
C158 "GRM033Z71C104KE14D" 0201_cap#1 1715.25,1141.97 r180 top value="0.1 uF"
C159 "CGA1A2X7R1A103K030BA" 0201_cap#1 1873.23,1183.12 r180 top value="0.01 uF"
C160 "C1005X5R1E105K050BC" 0402L_cap#2 1981.93,1366.3 r180 top value="1 uF"
C161 "C1005X5R1E105K050BC" 0402L_cap#2 2087.28,1276.61 r270 top value="1 uF"
C163 "CGA1A2X7R1A103K030BA" 0201_cap#1 2025.23,1234.09 r90 top value="0.01 uF"
C164 "C1005X5R1E104K050BC" 0402L_cap#1 4738.91,211.18 r180 top value="0.1 uF"
C165 "C1005X5R1E104K050BC" 0402L_cap#2 577.89,895.37 r180 top value="0.1 uF"
C166 "C1005X5R1A475K050BE" 0402L_cap#1 605.19,1422.27 r90 bottom value="4.7 uF"
C167 "C1005X5R1E104K050BC" 0402L_cap#1 640.19,1422.27 r90 bottom value="0.1 uF"
C168 "C1005X5R1E104K050BC" 0402L_cap#1 375.7,1328.17 r270 top value="0.1 uF"
C169 "C1005X5R1E104K050BC" 0402L_cap#1 159.16,1328.17 r270 top value="0.1 uF"
C170 "C1005X5R1E104K050BC" 0402L_cap#1 277.27,1627.78 r90 top value="0.1 uF"
C171 "C1005X5R1E104K050BC" 0402L_cap#1 159.16,1627.78 r90 top value="0.1 uF"
C172 "C1005X5R1E104K050BC" 0402L_cap#1 138.45,1508.23 r180 top value="0.1 uF"
C173 "C1005X5R1E104K050BC" 0402L_cap#2 415.07,1050.31 r270 top value="0.1 uF"
C174 "C1005X5R1A475K050BE" 0402L_cap#1 576.25,1692.04 r0 bottom value="4.7 uF"
C175 "C1005X5R1E104K050BC" 0402L_cap#1 576.25,1657.04 r0 bottom value="0.1 uF"
C176 "C1005X5R1E104K050BC" 0402L_cap#2 203.96,992.36 r0 top value="0.1 uF"
C177 "C1005X5R1E104K050BC" 0402L_cap#1 80.42,1697.47 r0 bottom value="0.1 uF"
C178 "C1005X5R1A475K050BE" 0402L_cap#1 80.42,1732.47 r0 bottom value="4.7 uF"
C180 "C1005X5R1E104K050BC" 0402L_cap#2 490.07,2032.19 r90 top value="0.1 uF"
C181 "GJM0335C1E180GB01D" 0201_cap#2 459.75,1619.95 r270 top value="18 pF"
C182 "GJM0335C1E180GB01D" 0201_cap#2 459.75,1572.22 r90 top value="18 pF"
C183 "C1005X5R1E104K050BC" 0402L_cap#2 123.69,992.5 r180 top value="0.1 uF"
C184 "C1005X5R1E104K050BC" 0402L_cap#2 722.31,1195.75 r0 top value="0.1 uF"
C185 "C1005X5R1E104K050BC" 0402L_cap#2 767.74,839.13 r0 top value="0.1 uF"
C186 "C1005X5R1E104K050BC" 0402L_cap#2 807.43,891.37 r90 top value="0.1 uF"
C187 "C1005X5R1E104K050BC" 0402L_cap#2 2544.26,1025.93 r90 bottom value="0.1 uF"
C188 "C1005X5R1E104K050BC" 0402L_cap#2 2546.55,947.6 r270 bottom value="0.1 uF"
C189 "C1005X5R1E104K050BC" 0402L_cap#2 581.13,1045.83 r90 top value="0.1 uF"
C190 "C1005X5R1E104K050BC" 0402L_cap#2 620.5,1025.83 r270 top value="0.1 uF"
D1 "LTST-C191TGKT" LED_LTST-C190-Green 1428.42,541.25 r180 top
D2 "LTST-C191TGKT" LED_LTST-C190-Green 910.57,498.46 r0 top
D3 "SMBJ15CA" SMBJ15CA 1244,252.99 r90 bottom
D4 "MBR130T1G" SOD-123 1737.17,466.17 r0 bottom
D5 "RBR3LAM40ATR" SOD-128 2140.53,96.58 r180 top
D6 "SDM40E20LC-7" SOT-323-DIO 4630,170 r0 top
D7 "LTST-C191TGKT" LED_LTST-C190-Green 178.85,2434.74 r180 top
F1 "SF-1206FP250-2" SF-1206F500M-2_1206 1593.61,330.05 r270 bottom
F2 "BNX002-11" FIL_BNX002-11 910.57,254.71 r0 bottom
FB1 "BLE18PS080SN1D" 0603L 1580.28,498.18 r90 bottom value=-
FB2 "BLE18PS080SN1D" 0603L 3045.13,584.99 r90 top value=-
FB3 "BLE18PS080SN1D" 0603L 3600.39,459.91 r90 top value=-
FB4 "BLE18PS080SN1D" 0603L 3397.46,459.91 r90 top value=-
FB5 "BLE18PS080SN1D" 0603L 4021.7,459.91 r90 top value=-
FB6 "BLE18PS080SN1D" 0603L 3820.14,459.91 r90 top value=-
FB8 "BLE18PS080SN1D" 0603L 2888.5,320.18 r270 top value=-
FB11 "NFZ15SG151SN11D" 0402L#1 675.19,1422.27 r90 bottom value=-
FB12 "NFZ15SG151SN11D" 0402L#1 576.25,1727.04 r0 bottom value=-
FC1 "NFM31PC276B0J3L" NFM31PC#1 3625.19,611.64 r90 top value=27uF
FC2 "NFM31PC276B0J3L" NFM31PC#1 3422.26,611.64 r90 top value=27uF
FC3 "NFM31PC276B0J3L" NFM31PC#1 4046.5,611.64 r90 top value=27uF
FC4 "NFM31PC276B0J3L" NFM31PC#1 3844.94,611.64 r90 top value=27uF
FC5 "NFM31PC276B0J3L" NFM31PC#2 2179.39,549.31 r90 top value=27uF
FC6 "NFM31PC276B0J3L" NFM31PC#1 2392,540.1 r90 top value=27uF
FID1 "Fiducial Mark" Fiducial10-20#1 893.16,280.52 r0 top
FID2 "Fiducial Mark" Fiducial10-20#2 300,150 r0 top
FID3 "Fiducial Mark" Fiducial10-20#3 4900,2616.54 r0 top
H5 "2069-440-SS" FP-2116-440-AL_STANDOFF_HEX_1-4-MFG 150,150 r180 bottom
H6 "2069-440-SS" FP-2116-440-AL_STANDOFF_HEX_1-4-MFG 150,2566.54 r180 bottom
J1 "RAPC722X" RAPC722X -22.33,498.46 r0 bottom
J2 "132134-15" FP-132134-15_CONN_SMA_JACK-MFG 2845.89,2474.15 r0 top
J3 "TSW-102-14-S-D" PBC02DAAN 2395.89,2524.15 r270 top
J4 "132134-15" FP-132134-15_CONN_SMA_JACK-MFG 1197.5,2358.27 r0 top
J5 "132134-15" FP-132134-15_CONN_SMA_JACK-MFG 1197.5,1858.27 r0 top
J6 "132134-15" FP-132134-15_CONN_SMA_JACK-MFG 1870.59,1608.27 r0 top
J7 "132134-15" FP-132134-15_CONN_SMA_JACK-MFG 1197.5,1358.27 r0 top
J8 "132134-15" FP-132134-15_CONN_SMA_JACK-MFG 1197.5,858.27 r0 top
J9 "ASP-134488-01" SAMTEC_ASP-134488-01 4686.42,1358.27 r90 bottom locked
J10 "USB4105-GF-A" FP-USB4105-GF-A_CONN_USB_9MM58_7MM53-MFG 155.12,2202.44 r270 top
L1 "LQP03HQ2N0B02D" 0201#1 2601.25,1737.9 r0 top value="2 nH"
L2 "LQP03HQ2N0B02D" 0201#1 2601.25,1714.86 r0 top value="2 nH"
L3 "LQP03HQ2N0B02D" 0201#1 2601.75,1478.35 r0 top value="2 nH"
L4 "LQP03HQ2N0B02D" 0201#1 2601.75,1501.97 r0 top value="2 nH"
L5 "026011C-12NXJRU" 026011C 2100.27,2142.9 r0 top value="12 nH"
L6 "026011C-9N0XJRU" 026011C 2174.19,2141.82 r0 top value="9 nH"
L7 "026011C-12NXJRU" 026011C 2100.27,2075.58 r0 top value="12 nH"
L8 "026011C-9N0XJRU" 026011C 2174.01,2074.68 r0 top value="9 nH"
L9 "026011C-12NXJRU" 026011C 2100.19,1142.36 r0 top value="12 nH"
L10 "026011C-9N0XJRU" 026011C 2174.01,1142 r0 top value="9 nH"
L11 "026011C-12NXJRU" 026011C 2100.19,1075.03 r0 top value="12 nH"
L12 "026011C-9N0XJRU" 026011C 2174.01,1074.68 r0 top value="9 nH"
LBL1 "THT-14-423-10" Label_650x200 3784.24,1430.19 r0 top
Logo1 "FDL Logo" FDL_Small 4707.41,459.26 r0 top
Logo2 "FCC disclaimer" FCC_disclaimer_stacked 3316.64,2135.26 r180 bottom
Logo3 "ESD Overlay" ESD_Overlay_Medium 3214.48,2014.91 r0 top
Logo4 "WEEE" WEEE_Minimum 3701.47,2031.93 r180 bottom
LOGO5 "CE Mark" CE_Mark_5mm 3697.33,1668.94 r180 bottom
Logo6 "Texas Instruments" TI_Stacked_Overlay_Small 3857.49,1651.6 r0 top
NT1 "Net-Tie" Net-Tie_5milWide_60milLong 571.16,992.36 r0 bottom net-tie
NT2 "Net-Tie" Net-Tie_5milWide_60milLong 591.83,949.74 r0 bottom net-tie
PP1 "Probe Point" ProbePoint_TH_40mil 4511.42,111.66 r90 top
PP2 "Probe Point" ProbePoint_TH_40mil 3022.21,670.36 r180 top
PP3 "Probe Point" ProbePoint_TH_40mil 3695.22,538.58 r180 top
PP4 "Probe Point" ProbePoint_TH_40mil 3352.14,538.58 r180 top
PP5 "Probe Point" ProbePoint_TH_40mil 4116.53,538.58 r180 top
PP6 "Probe Point" ProbePoint_TH_40mil 3774.82,538.58 r180 top
PP8 "Probe Point" ProbePoint_TH_40mil 2911.42,234.81 r0 top
PP11 "Probe Point" ProbePoint_TH_40mil 4340.47,2563.03 r90 top
PP12 "Probe Point" ProbePoint_TH_40mil 753,1547.55 r0 top
PP13 "Probe Point" ProbePoint_TH_40mil 753,1607.55 r0 top
PP14 "Probe Point" ProbePoint_TH_40mil 753,1667.55 r0 top
Q1 "MMBT3904WT1G" SOT-323 979.47,567.1 r270 bottom
Q2 "CSD15571Q2" DQK0006C 1369.81,168.39 r270 bottom
R1 "ERA-2AED102X" 0402L#1 959.79,498.46 r0 bottom value="1 kΩ"
R2 "ERJ-2RKF1004X" 0402L#1 1726.66,197.26 r180 bottom value="1 MΩ"
R3 "ERJ-H2RF4701X" 0402L#1 1379.68,476.33 r0 top value="4.7 kΩ"
R4 "ERA-2APB2672X" 0402L#1 1857.57,425.96 r180 bottom value="26.7 kΩ"
R5 "ERJ-2RKF1623X" 0402L#1 1698.31,83 r0 bottom value="162 kΩ"
R6 "ERJ-2RKF1002X" 0402L#1 1878.52,630.8 r90 top value="10 kΩ"
R7 "ERJ-2RKF1002X" 0402L#1 1677.3,652.3 r180 top value="10 kΩ"
R8 "ERJ-2RKF1002X" 0402L#1 1461.3,617.12 r0 bottom value="10 kΩ"
R9 "ERA-2APB562X" 0402L#1 1249.79,578.11 r270 bottom value="5.6 kΩ"
R10 "ERA-2AEB3742X" 0402L#1 1878.52,555.84 r270 top value="37.4 kΩ"
R11 "ERA-2ARB123X" 0402L#1 1289.77,620.73 r270 bottom value="12 kΩ"
R12 "ERA-2ARB123X" 0402L#1 1913.52,595.21 r270 top value="12 kΩ"
R13 "ERJ-2RKF1002X" 0402L#1 3031.27,137.75 r270 top value="10 kΩ"
R14 "ERJ-2RKF1002X" 0402L#1 3201.64,137.75 r270 top value="10 kΩ"
R15 "ERA-2AEB8062X" 0402L#1 3167.64,137.75 r90 top value="80.6 kΩ"
R16 "ERA-2AEB9311X" 0402L#1 3099.64,137.75 r270 top value="9.31 kΩ"
R17 "ERJ-2GE0R00X" 0402L#1 3235.64,177.12 r270 top value="0 Ω"
R18 "ERA-2AEB4871X" 0402L#1 3133.64,137.75 r90 top value="4.87 kΩ"
R19 "ERJ-2RKF1002X" 0402L#1 3710.23,106.52 r0 top value="10 kΩ"
R20 "ERJ-3BWFR020V" 0603L 3650.39,404.79 r270 top value="20 mΩ"
R21 "ERJ-2RKF5112X" 0402L#1 3624.4,296.76 r0 top value="51.1 kΩ"
R22 "ERJ-2RKF1002X" 0402L#1 3656.69,71.52 r180 top value="10 kΩ"
R23 "ERJ-1GN0R00C" 0201#2 3549.82,105.58 r90 bottom value="0 Ω"
R24 "ERJ-2RKF1242X" 0402L#1 3604.71,317.81 r270 bottom value="12.4 kΩ"
R25 "ERJ-S080R00V" 1206L 3477.28,529.83 r0 bottom value="0 Ω"
R26 "ERJ-2GE0R00X" 0402L#1 3696.06,71.52 r180 bottom value="0 Ω"
R27 "ERA-2APB8061X" 0402L#1 3710.23,335.73 r180 top value="8.06 kΩ"
R28 "ERJ-2RKF1002X" 0402L#1 3507.3,106.52 r0 top value="10 kΩ"
R29 "ERJ-3BWFR020V" 0603L 3447.46,404.79 r270 top value="20 mΩ"
R30 "ERJ-2RKF5112X" 0402L#1 3421.97,296.76 r0 top value="51.1 kΩ"
R31 "ERJ-2RKF1002X" 0402L#1 3453.76,71.52 r180 top value="10 kΩ"
R32 "ERJ-1GN0R00C" 0201#2 3349.82,105.58 r90 bottom value="0 Ω"
R33 "ERJ-2RKF1242X" 0402L#1 3402.29,316.45 r270 bottom value="12.4 kΩ"
R34 "ERJ-2GE0R00X" 0402L#1 3493.13,71.52 r180 bottom value="0 Ω"
R35 "ERA-2APB8061X" 0402L#1 3507.3,335.73 r180 top value="8.06 kΩ"
R36 "ERJ-2RKF1002X" 0402L#1 4131.54,106.52 r0 top value="10 kΩ"
R37 "ERJ-3BWFR020V" 0603L 4071.7,404.79 r270 top value="20 mΩ"
R38 "ERJ-2RKF8872X" 0402L#1 4045.71,296.76 r0 top value="88.7 kΩ"
R39 "ERJ-2RKF1002X" 0402L#1 4077.99,71.52 r180 top value="10 kΩ"
R40 "ERJ-1GN0R00C" 0201#2 3971.13,105.58 r90 bottom value="0 Ω"
R41 "ERJ-2RKF1242X" 0402L#1 4026.02,317.81 r270 bottom value="12.4 kΩ"
R42 "ERJ-S080R00V" 1206L 3899.58,529.83 r0 bottom value="0 Ω"
R43 "ERJ-2GE0R00X" 0402L#1 4117.36,71.52 r180 bottom value="0 Ω"
R44 "ERA-2ARB123X" 0402L#1 4131.54,335.73 r180 top value="12 kΩ"
R45 "ERJ-2RKF1002X" 0402L#1 3929.98,106.52 r0 top value="10 kΩ"
R46 "ERJ-3BWFR020V" 0603L 3870.14,404.79 r270 top value="20 mΩ"
R47 "ERJ-2RKF8872X" 0402L#1 3844.66,296.76 r0 top value="88.7 kΩ"
R48 "ERJ-2RKF1002X" 0402L#1 3876.44,71.52 r180 top value="10 kΩ"
R49 "ERJ-1GN0R00C" 0201#2 3749.82,105.58 r90 bottom value="0 Ω"
R50 "ERJ-2RKF1242X" 0402L#1 3824.97,316.45 r270 bottom value="12.4 kΩ"
R51 "ERJ-2GE0R00X" 0402L#1 3915.81,71.52 r180 bottom value="0 Ω"
R52 "ERA-2ARB123X" 0402L#1 3929.98,335.73 r180 top value="12 kΩ"
R53 "ERA-2AEB2322X" 0402L#2 2310.83,116.54 r180 top value="23.2 kΩ"
R54 "CRCW20100000Z0EF" 2010 2049.3,278.02 r270 top value=0
R55 "ERA-2AEB3240X" 0402L#2 2288.88,237.05 r0 bottom value="324 Ω"
R56 "ERA-2AEB104X" 0402L#1 2381.2,116.54 r180 top value="100 kΩ"
R57 "ERA-2AEB104X" 0402L#2 2222.15,269.97 r270 top value="100 kΩ"
R58 "CRCW20100000Z0EF" 2010 2049.3,529.12 r270 top value=0
R59 "ERJ-6GEY0R00V" 0805L 2389.13,397.07 r90 top value="0 Ω"
R60 "ERJ-1GN0R00C" 0201#2 2989.41,888.13 r0 bottom value="0 Ω"
R61 "ERJ-2RKF1002X" 0402L#2 729.47,2611.54 r180 bottom value="10 kΩ"
R62 "ERJ-2RKF1002X" 0402L#2 419.23,2611.54 r0 bottom value="10 kΩ"
R63 "ERJ-1GN0R00C" 0201#2 3573.44,219.64 r90 bottom value="0 Ω"
R64 "ERJ-2RKF1002X" 0402L#1 2937.37,767.42 r90 top value="10 kΩ"
R65 "ERJ-2RKF1002X" 0402L#1 2733,767.42 r90 top value="10 kΩ"
R66 "ERJ-U020R00X" 0402L#2 2767,767.42 r90 top value="0 Ω"
R67 "ERA-2AEB8062X" 0402L#1 2801,767.42 r270 top value="80.6 kΩ"
R68 "ERA-2AEB7871X" 0402L#1 2835,767.42 r90 top value="7.87 kΩ"
R69 "ERJ-2GE0R00X" 0402L#1 2697.04,728.26 r90 top value="0 Ω"
R70 "ERA-2ARB182X" 0402L#1 2869,767.42 r270 top value="1.8 kΩ"
R71 "ERJ-1GN0R00C" 0201#2 3620.68,161.47 r0 bottom value="0 Ω"
R72 "ERJ-1GN0R00C" 0201#2 3994.75,219.64 r90 bottom value="0 Ω"
R73 "ERJ-2RKF1002X" 0402L#1 2380.54,166.83 r270 bottom value="10 kΩ"
R74 "ERJ-2GE0R00X" 0402L#1 2430.22,186.51 r0 bottom value="0 Ω"
R75 "ERJ-2GE0R00X" 0402L#1 2380.54,206.2 r270 bottom value="0 Ω"
R76 "ERJ-1GN0R00C" 0201#2 4041.91,161.38 r0 bottom value="0 Ω"
R77 "ERJ-1GN0R00C" 0201#2 3018.05,850.19 r90 bottom value="0 Ω"
R78 "ERJ-2RKF1002X" 0402L#2 494.03,2399.8 r180 bottom value="10 kΩ"
R79 "ERJ-2GE0R00X" 0402L#2 477.93,867.75 r90 bottom value="0 Ω"
R80 "ERJ-2GE0R00X" 0402L#2 477.93,828.38 r90 bottom value="0 Ω"
R81 "ERJ-1GN0R00C" 0201#2 3373.44,219.64 r90 bottom value="0 Ω"
R82 "ERJ-1GN0R00C" 0201#1 3084.25,1572.74 r0 top value="0 Ω"
R83 "ERJ-1GN0R00C" 0201#1 3084.25,1596.43 r0 top value="0 Ω"
R84 "ERJ-1GN0R00C" 0201#1 2786.79,1374.02 r270 top value="0 Ω"
R85 "ERJ-1GN0R00C" 0201#1 2763.1,1374.02 r270 top value="0 Ω"
R86 "ERJ-1GN0R00C" 0201#1 2834.16,1374.02 r270 top value="0 Ω"
R87 "ERJ-1GN0R00C" 0201#1 2810.5,1374.02 r270 top value="0 Ω"
R88 "ERJ-1GN0R00C" 0201#1 2881.5,1374.02 r270 top value="0 Ω"
R89 "ERJ-1GN0R00C" 0201#1 2857.87,1374.02 r270 top value="0 Ω"
R90 "ERJ-1GN0R00C" 0201#1 2928.87,1374.02 r270 top value="0 Ω"
R91 "ERJ-1GN0R00C" 0201#1 2905.21,1374.02 r270 top value="0 Ω"
R92 "ERJ-1GN0R00C" 0201#1 2976.27,1374.02 r270 top value="0 Ω"
R93 "ERJ-1GN0R00C" 0201#1 2952.58,1374.02 r270 top value="0 Ω"
R94 "ERJ-1GN0R00C" 0201#1 3084.25,1430.63 r0 top value="0 Ω"
R95 "ERJ-1GN0R00C" 0201#1 3084.25,1454.32 r0 top value="0 Ω"
R96 "ERJ-1GN0R00C" 0201#1 3084.25,1478 r0 top value="0 Ω"
R97 "ERJ-1GN0R00C" 0201#1 3084.25,1501.69 r0 top value="0 Ω"
R98 "ERJ-1GN0R00C" 0201#1 3084.25,1525.37 r0 top value="0 Ω"
R99 "ERJ-1GN0R00C" 0201#1 3084.25,1549.06 r0 top value="0 Ω"
R100 "ERJ-1GN0R00C" 0201#1 3084.25,1691.17 r0 top value="0 Ω"
R101 "ERJ-1GN0R00C" 0201#1 3084.25,1667.48 r0 top value="0 Ω"
R102 "ERJ-1GN0R00C" 0201#1 3084.25,1738.54 r0 top value="0 Ω"
R103 "ERJ-1GN0R00C" 0201#1 3084.25,1714.85 r0 top value="0 Ω"
R104 "ERJ-1GN0R00C" 0201#1 3084.25,1785.91 r0 top value="0 Ω"
R105 "ERJ-1GN0R00C" 0201#1 3084.25,1762.22 r0 top value="0 Ω"
R106 "ERJ-1GN0R00C" 0201#1 2976.27,1842.52 r90 top value="0 Ω"
R107 "ERJ-1GN0R00C" 0201#1 2952.58,1842.52 r90 top value="0 Ω"
R108 "ERJ-1GN0R00C" 0201#1 2928.9,1842.52 r90 top value="0 Ω"
R109 "ERJ-1GN0R00C" 0201#1 2905.21,1842.52 r90 top value="0 Ω"
R110 "ERJ-1GN0R00C" 0201#2 3420.68,161.47 r0 bottom value="0 Ω"
R111 "ERJ-2GE0R00X" 0402L#2 2638.33,1538.59 r270 bottom value="0 Ω"
R112 "ERJ-PA2F1002X" 0402L#1 2713.42,2172.97 r225 bottom value="10 kΩ"
R113 "ERJ-PA2F1002X" 0402L#1 2662.69,2073.3 r45 bottom value="10 kΩ"
R114 "ERJ-1GN0R00C" 0201#1 2881.53,1842.52 r90 top value="0 Ω"
R115 "ERJ-1GN0R00C" 0201#1 2857.84,1842.52 r90 top value="0 Ω"
R116 "ERJ-1GN0R00C" 0201#2 3773.44,219.64 r90 bottom value="0 Ω"
R117 "ERJ-1GN0R00C" 0201#1 2834.16,1842.52 r90 top value="0 Ω"
R118 "ERJ-1GN0R00C" 0201#1 2810.47,1842.52 r90 top value="0 Ω"
R119 "ERJ-1GN0R00C" 0201#1 2786.79,1842.52 r90 top value="0 Ω"
R120 "ERJ-1GN0R00C" 0201#1 2763.1,1842.52 r90 top value="0 Ω"
R121 "ERJ-2GE0R00X" 0402L#2 2602.87,1519.69 r90 bottom value="0 Ω"
R122 "ERJ-PA2F1002X" 0402L#1 2737.69,2148.7 r45 bottom value="10 kΩ"
R123 "ERJ-PA2F1002X" 0402L#1 2638.42,2097.57 r225 bottom value="10 kΩ"
R124 "ERJ-2GE0R00X" 0402L#1 4205.16,2650 r180 top value="0 Ω"
R125 "ERJ-2RKF1002X" 0402L#2 3952.16,2609.21 r180 bottom value="10 kΩ"
R126 "ERJ-2GE0R00X" 0402L#1 4098.43,2650 r180 top value="0 Ω"
R127 "ERJ-2GE0R00X" 0402L#1 4275.16,2527.6 r180 top value="0 Ω"
R128 "ERJ-2GE0R00X" 0402L#1 4275.16,2602.4 r180 top value="0 Ω"
R129 "ERJ-U01F49R9C" 0201#2 2308.07,2141.82 r0 top value="49.9 Ω"
R130 "ERJ-U01F49R9C" 0201#2 2308.07,2074.72 r0 top value="49.9 Ω"
R131 "ERJ-1GNF4990C" 0201#1 2635.27,1726.38 r90 top value="499 Ω"
R132 "ERJ-1GNF33R0C" 0201#1 2423.83,1643.08 r90 bottom value="33 Ω"
R133 "ERJ-1GNF1000C" 0201#1 2589.99,1607.73 r90 top value="100 Ω"
R134 "ERJ-U01F49R9C" 0201#1 2072.59,1597.52 r90 bottom value="49.9 Ω"
R135 "ERJ-1GNF33R0C" 0201#1 2423.83,1573.46 r270 bottom value="33 Ω"
R136 "ERJ-1GNF4990C" 0201#1 2635.27,1490.16 r270 top value="499 Ω"
R137 "ERJ-U01F49R9C" 0201#2 2308.07,1141.82 r0 top value="49.9 Ω"
R138 "ERJ-U01F49R9C" 0201#2 2308.07,1074.72 r0 top value="49.9 Ω"
R139 "ERJ-2GE0R00X" 0402L#1 2600,1796.62 r180 bottom value="0 Ω"
R140 "ERJ-1GN0R00C" 0201#2 1648.81,2073.19 r0 top value="0 Ω"
R141 "ERJ-U01F22R6C" 0201#2 1759.27,2073.19 r0 top value="22.6 Ω"
R142 "ERJ-1GNF1270C" 0201#2 1804.45,2084.73 r270 top value="127 Ω"
R143 "ERJ-1GNF40R2C" 0201#2 1986.27,2140.75 r0 top value="40.2 Ω"
R144 "ERJ-1GNF3570C" 0201#2 1681.83,2084.21 r270 top value="357 Ω"
R145 "ERJ-U01F1002C" 0201#2 2064.3,2107.96 r90 top value="10 kΩ"
R146 "ERJ-1GN0R00C" 0201#2 1681.83,2129.57 r90 top value="0 Ω"
R147 "ERJ-1GN0R00C" 0201#2 1648.81,2140.59 r0 top value="0 Ω"
R148 "ERJ-1GNF66R5C" 0201#2 1759.66,2140.59 r0 top value="66.5 Ω"
R149 "ERJ-1GNF1270C" 0201#2 1804.45,2130.95 r90 top value="127 Ω"
R150 "ERJ-1GNF40R2C" 0201#2 1985.97,2074.93 r0 top value="40.2 Ω"
R151 "ERJ-2GEJ102X" 0402L#2 1918.93,2235.12 r0 top value="1 kΩ"
R152 "ERJ-2RKF5900X" 0402L#2 1849.56,2235.12 r0 top value="590 Ω"
R153 "ERJ-2RKF1002X" 0402L#2 1903.93,1962.56 r0 top value="10 kΩ"
R154 "ERJ-U01F1501C" 0201#2 2018.02,2086.74 r270 top value="1.5 kΩ"
R155 "ERJ-U01F1501C" 0201#2 2018.1,2128.94 r90 top value="1.5 kΩ"
R156 "ERJ-U01F1002C" 0201#2 2076.26,2326.3 r0 top value="10 kΩ"
R157 "ERJ-PA2F1002X" 0402L#2 1864.56,1962.56 r0 top value="10 kΩ"
R158 "ERJ-U01F22R6C" 0201#2 1884.25,2276.14 r90 top value="22.6 Ω"
R159 "ERJ-1GN0R00C" 0201#2 1649.2,1074.57 r0 top value="0 Ω"
R160 "ERJ-U01F22R6C" 0201#2 1759.66,1074.77 r0 top value="22.6 Ω"
R161 "ERJ-1GNF1270C" 0201#2 1804.45,1084.73 r270 top value="127 Ω"
R162 "ERJ-1GNF40R2C" 0201#2 1986.27,1140.75 r0 top value="40.2 Ω"
R163 "ERJ-1GNF3570C" 0201#2 1682.22,1085.59 r270 top value="357 Ω"
R164 "ERJ-U01F1002C" 0201#2 2064.38,1107.71 r90 top value="10 kΩ"
R165 "ERJ-1GN0R00C" 0201#2 1682.22,1130.95 r270 top value="0 Ω"
R166 "ERJ-1GN0R00C" 0201#2 1649.2,1141.97 r0 top value="0 Ω"
R167 "ERJ-1GNF66R5C" 0201#2 1760.06,1141.97 r0 top value="66.5 Ω"
R168 "ERJ-1GNF1270C" 0201#2 1804.41,1130.99 r90 top value="127 Ω"
R169 "ERJ-1GNF40R2C" 0201#2 1985.97,1074.93 r0 top value="40.2 Ω"
R170 "ERJ-2GEJ102X" 0402L#2 1918.93,1235.12 r0 top value="1 kΩ"
R171 "ERJ-2RKF5900X" 0402L#2 1849.56,1235.12 r0 top value="590 Ω"
R172 "ERJ-2RKF1002X" 0402L#2 1903.93,962.56 r0 top value="10 kΩ"
R173 "ERJ-U01F1501C" 0201#2 2018.1,1085.71 r270 top value="1.5 kΩ"
R174 "ERJ-U01F1501C" 0201#2 2018.18,1128.7 r90 top value="1.5 kΩ"
R175 "ERJ-U01F1002C" 0201#2 2076.26,1326.3 r0 top value="10 kΩ"
R176 "ERJ-PA2F1002X" 0402L#2 1864.56,962.56 r0 top value="10 kΩ"
R177 "ERJ-U01F22R6C" 0201#2 1884.25,1276.14 r90 top value="22.6 Ω"
R178 "ERJ-2GE0R00X" 0402L#2 353.29,1020.79 r90 bottom value="0 Ω"
R179 "ERJ-2GE0R00X" 0402L#2 353.29,981.42 r90 bottom value="0 Ω"
R180 "ERJ-2GE0R00X" 0402L#1 4251,762 r0 bottom value="0 Ω"
R181 "ERJ-2GE0R00X" 0402L#1 4251,727 r0 bottom value="0 Ω"
R182 "ERJ-3GEY0R00V" 0603L 4888.98,383.27 r180 top value="0 Ω"
R183 "ERJ-3GEY0R00V" 0603L 4710.24,2365.39 r180 top value="0 Ω"
R184 "ERJ-2GEJ472X" 0402L#1 4893.16,297.98 r0 top value="4.7 kΩ"
R185 "ERJ-H2RF4701X" 0402L#1 4893.16,228.61 r180 top value="4.7 kΩ"
R186 "ERJ-H2RF4701X" 0402L#1 4893.16,263.3 r180 top value="4.7 kΩ"
R187 "ERJ-H2RF4701X" 0402L#1 4893.16,331.98 r180 top value="4.7 kΩ"
R188 "ERA-2AED102X" 0402L#2 669.05,1022.73 r270 bottom value="1 kΩ"
R189 "ERJ-2GE0R00X" 0402L#2 304.91,1090.17 r90 top value="0 Ω"
R190 "ERJ-2GE0R00X" 0402L#2 304.91,1050.8 r90 top value="0 Ω"
R191 "ERJ-2GE0R00X" 0402L#1 4746.42,860.24 r90 top value="0 Ω"
R192 "ERJ-H3GJ101V" 0603L 4541.93,2302.75 r315 top value="100 Ω"
R193 "ERJ-2GE0R00X" 0402L#1 4251,832 r0 bottom value="0 Ω"
R194 "ERJ-2GE0R00X" 0402L#1 4286.36,1258.67 r0 bottom value="0 Ω"
R195 "ERJ-2GE0R00X" 0402L#2 4286.36,1208.67 r0 bottom value="0 Ω"
R196 "ERJ-2RKF1002X" 0402L#2 748.06,746.89 r270 bottom value="10 kΩ"
R197 "ERJ-2GE0R00X" 0402L#1 4575.34,1147.19 r225 top value="0 Ω"
R198 "ERJ-2GE0R00X" 0402L#1 4547.5,1097.19 r315 top value="0 Ω"
R199 "ERJ-2GE0R00X" 0402L#1 4251,902 r0 bottom value="0 Ω"
R200 "ERJ-2GE0R00X" 0402L#1 4251,937 r0 bottom value="0 Ω"
R201 "ERJ-2GE0R00X" 0402L#1 4251,797 r0 bottom value="0 Ω"
R204 "ERJ-2GE0R00X" 0402L#1 4251,867 r0 bottom value="0 Ω"
R207 "ERJ-H2RF4701X" 0402L#2 577.89,782.1 r180 bottom value="4.7 kΩ"
R208 "ERJ-H2RF1000X" 0402L#2 518.83,930.06 r90 bottom value="100 Ω"
R209 "ERJ-2RKF1002X" 0402L#2 507.33,1085.2 r270 bottom value="10 kΩ"
R210 "ERJ-H2RF4701X" 0402L#2 375.7,1085.63 r0 bottom value="4.7 kΩ"
R211 "ERJ-H2RF1000X" 0402L#2 489.44,992.36 r0 bottom value="100 Ω"
R212 "ERJ-2GE0R00X" 0402L#1 564.43,1310.65 r270 bottom value="0 Ω"
R213 "ERJ-2GE0R00X" 0402L#2 465.38,1141.3 r270 bottom value="0 Ω"
R214 "ERJ-2GE0R00X" 0402L#2 430.38,1140.31 r270 bottom value="0 Ω"
R215 "ERJ-2GE0R00X" 0402L#2 395.38,1140.31 r270 bottom value="0 Ω"
R216 "ERJ-2RKF1002X" 0402L#2 584.12,1290.97 r180 top value="10 kΩ"
R217 "ERJ-2RKF2201X" 0402L#2 203.96,1085.63 r180 bottom value="2.2 kΩ"
R218 "ERJ-2GE0R00X" 0402L#2 258.64,1140.31 r270 bottom value="0 Ω"
R219 "ERJ-2GE0R00X" 0402L#2 223.64,1140.31 r270 bottom value="0 Ω"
